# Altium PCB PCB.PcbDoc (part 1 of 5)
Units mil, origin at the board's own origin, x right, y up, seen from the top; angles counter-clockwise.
Board outline 8070.87 x 4448.94 mil, 4 copper layers (Top Layer, Layer 1, Layer 2, Bottom Layer), stack 23.756 mil thick; 263 components, 330 nets, 1677 pads, 1186 vias.
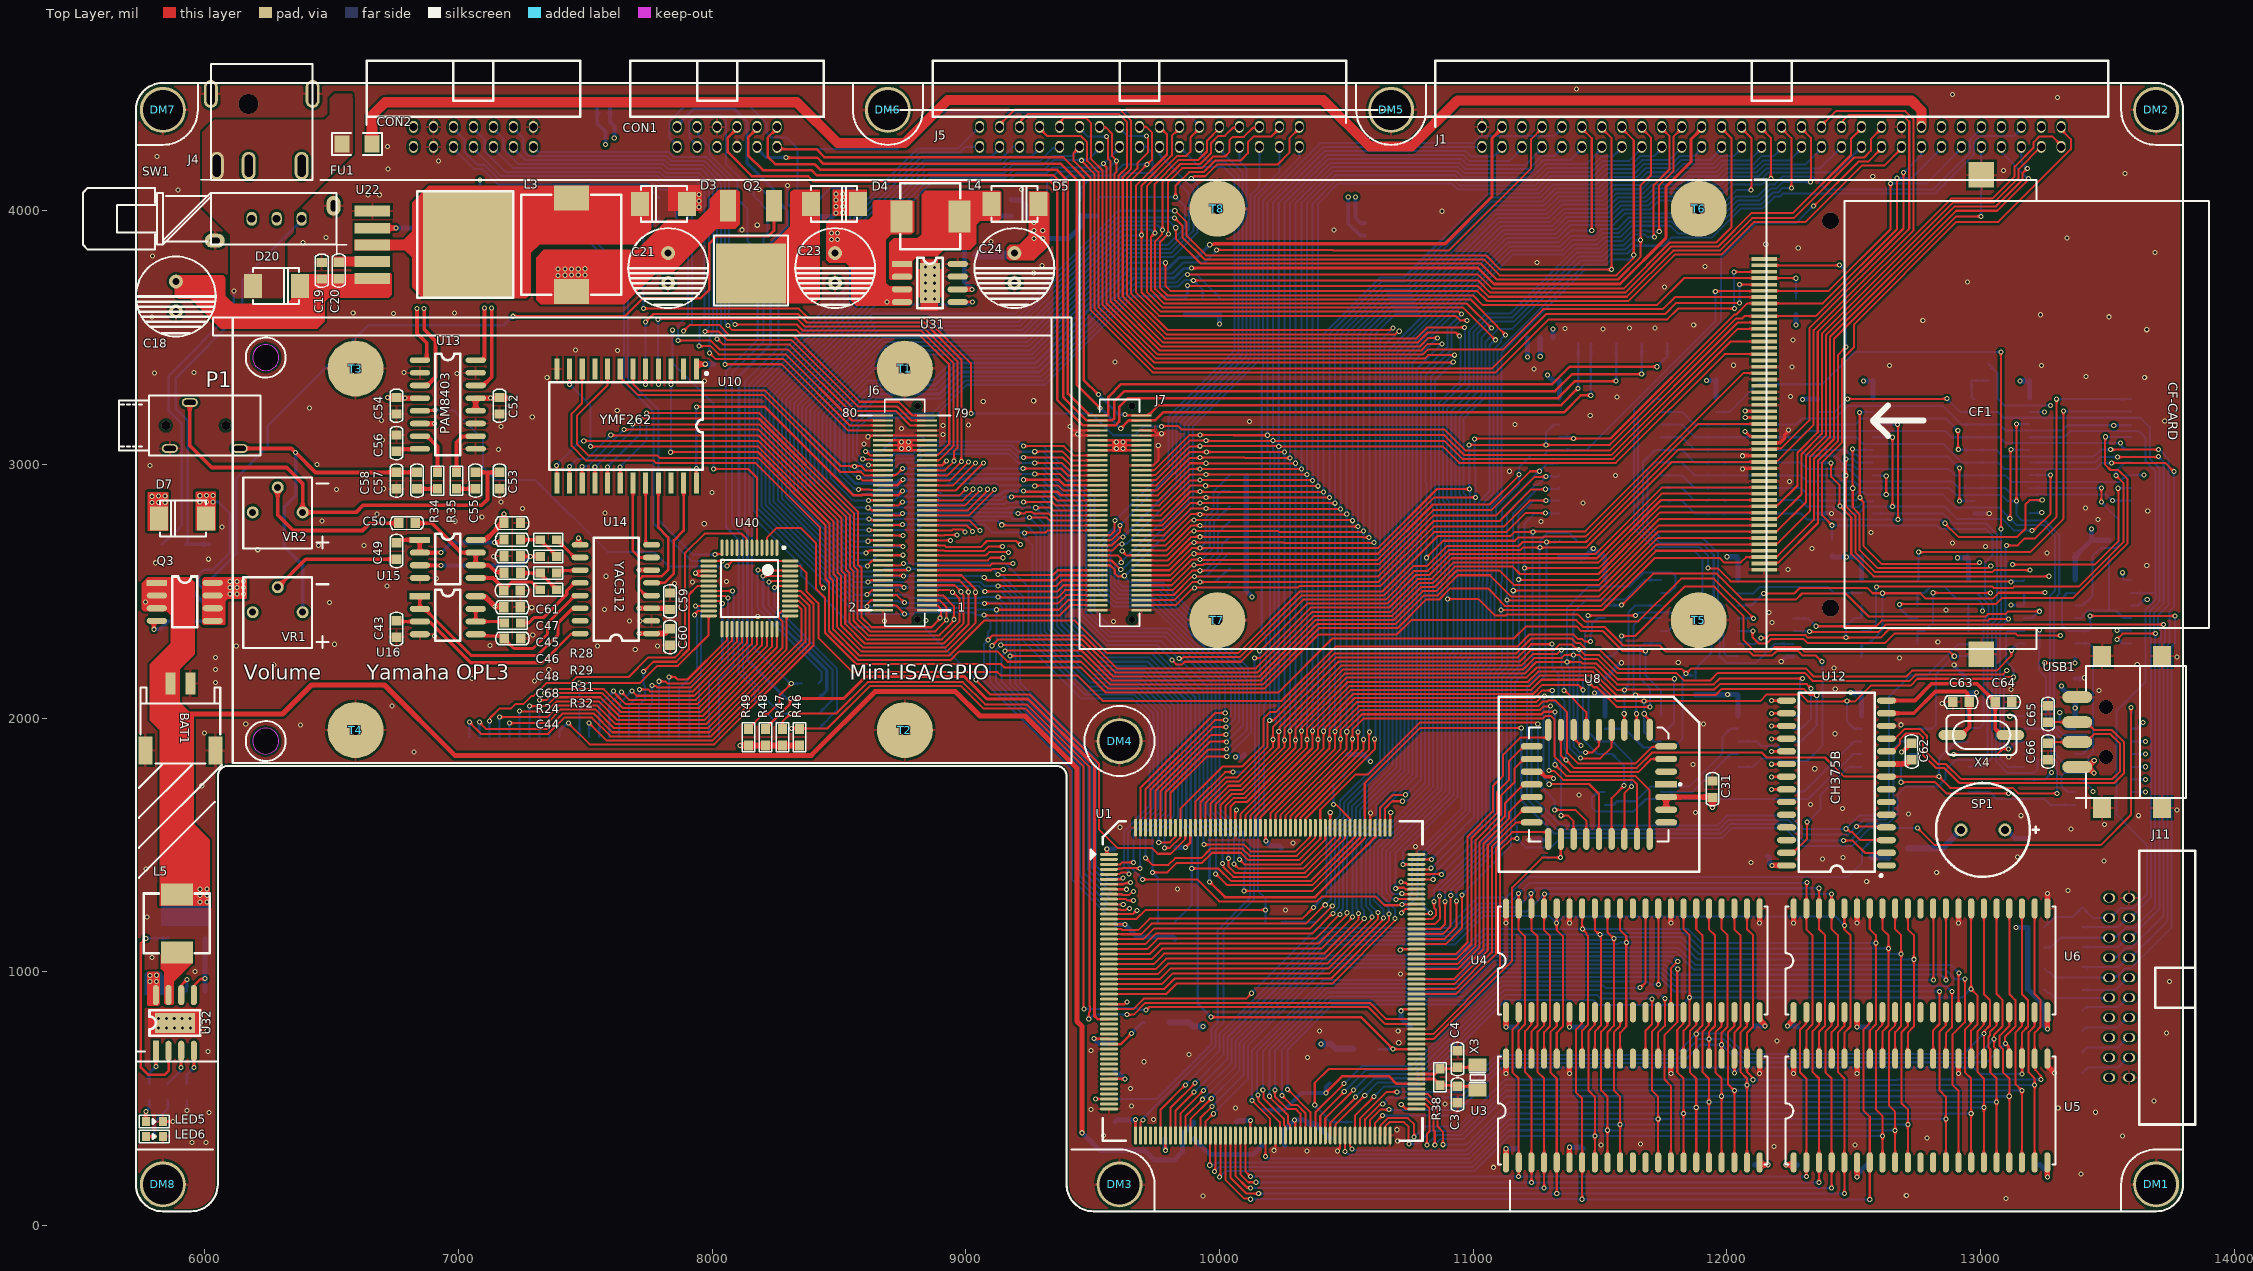
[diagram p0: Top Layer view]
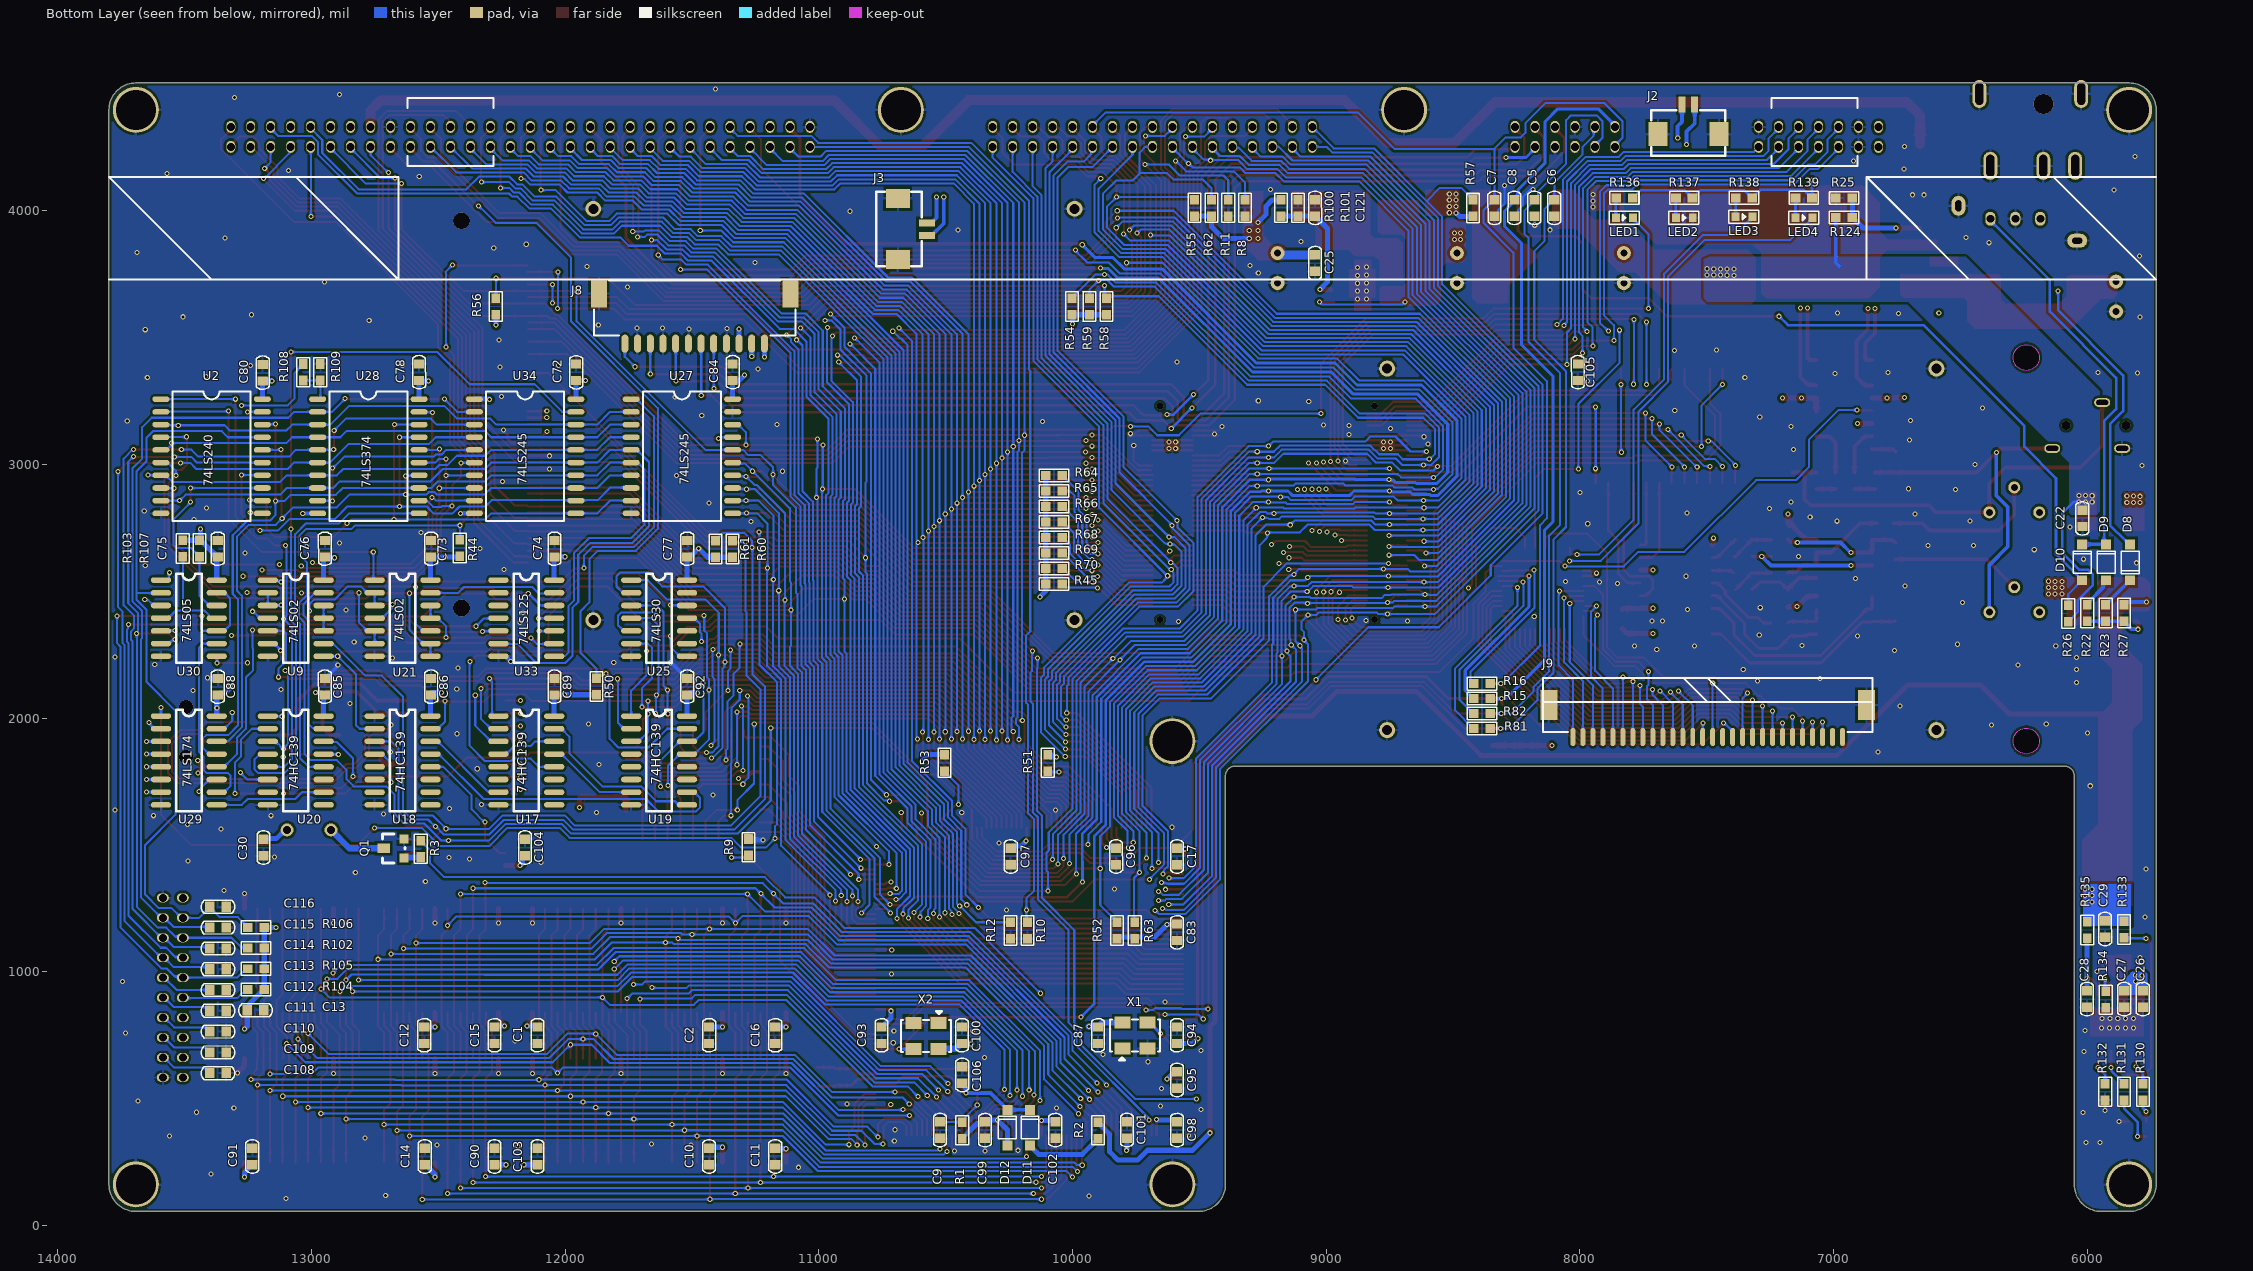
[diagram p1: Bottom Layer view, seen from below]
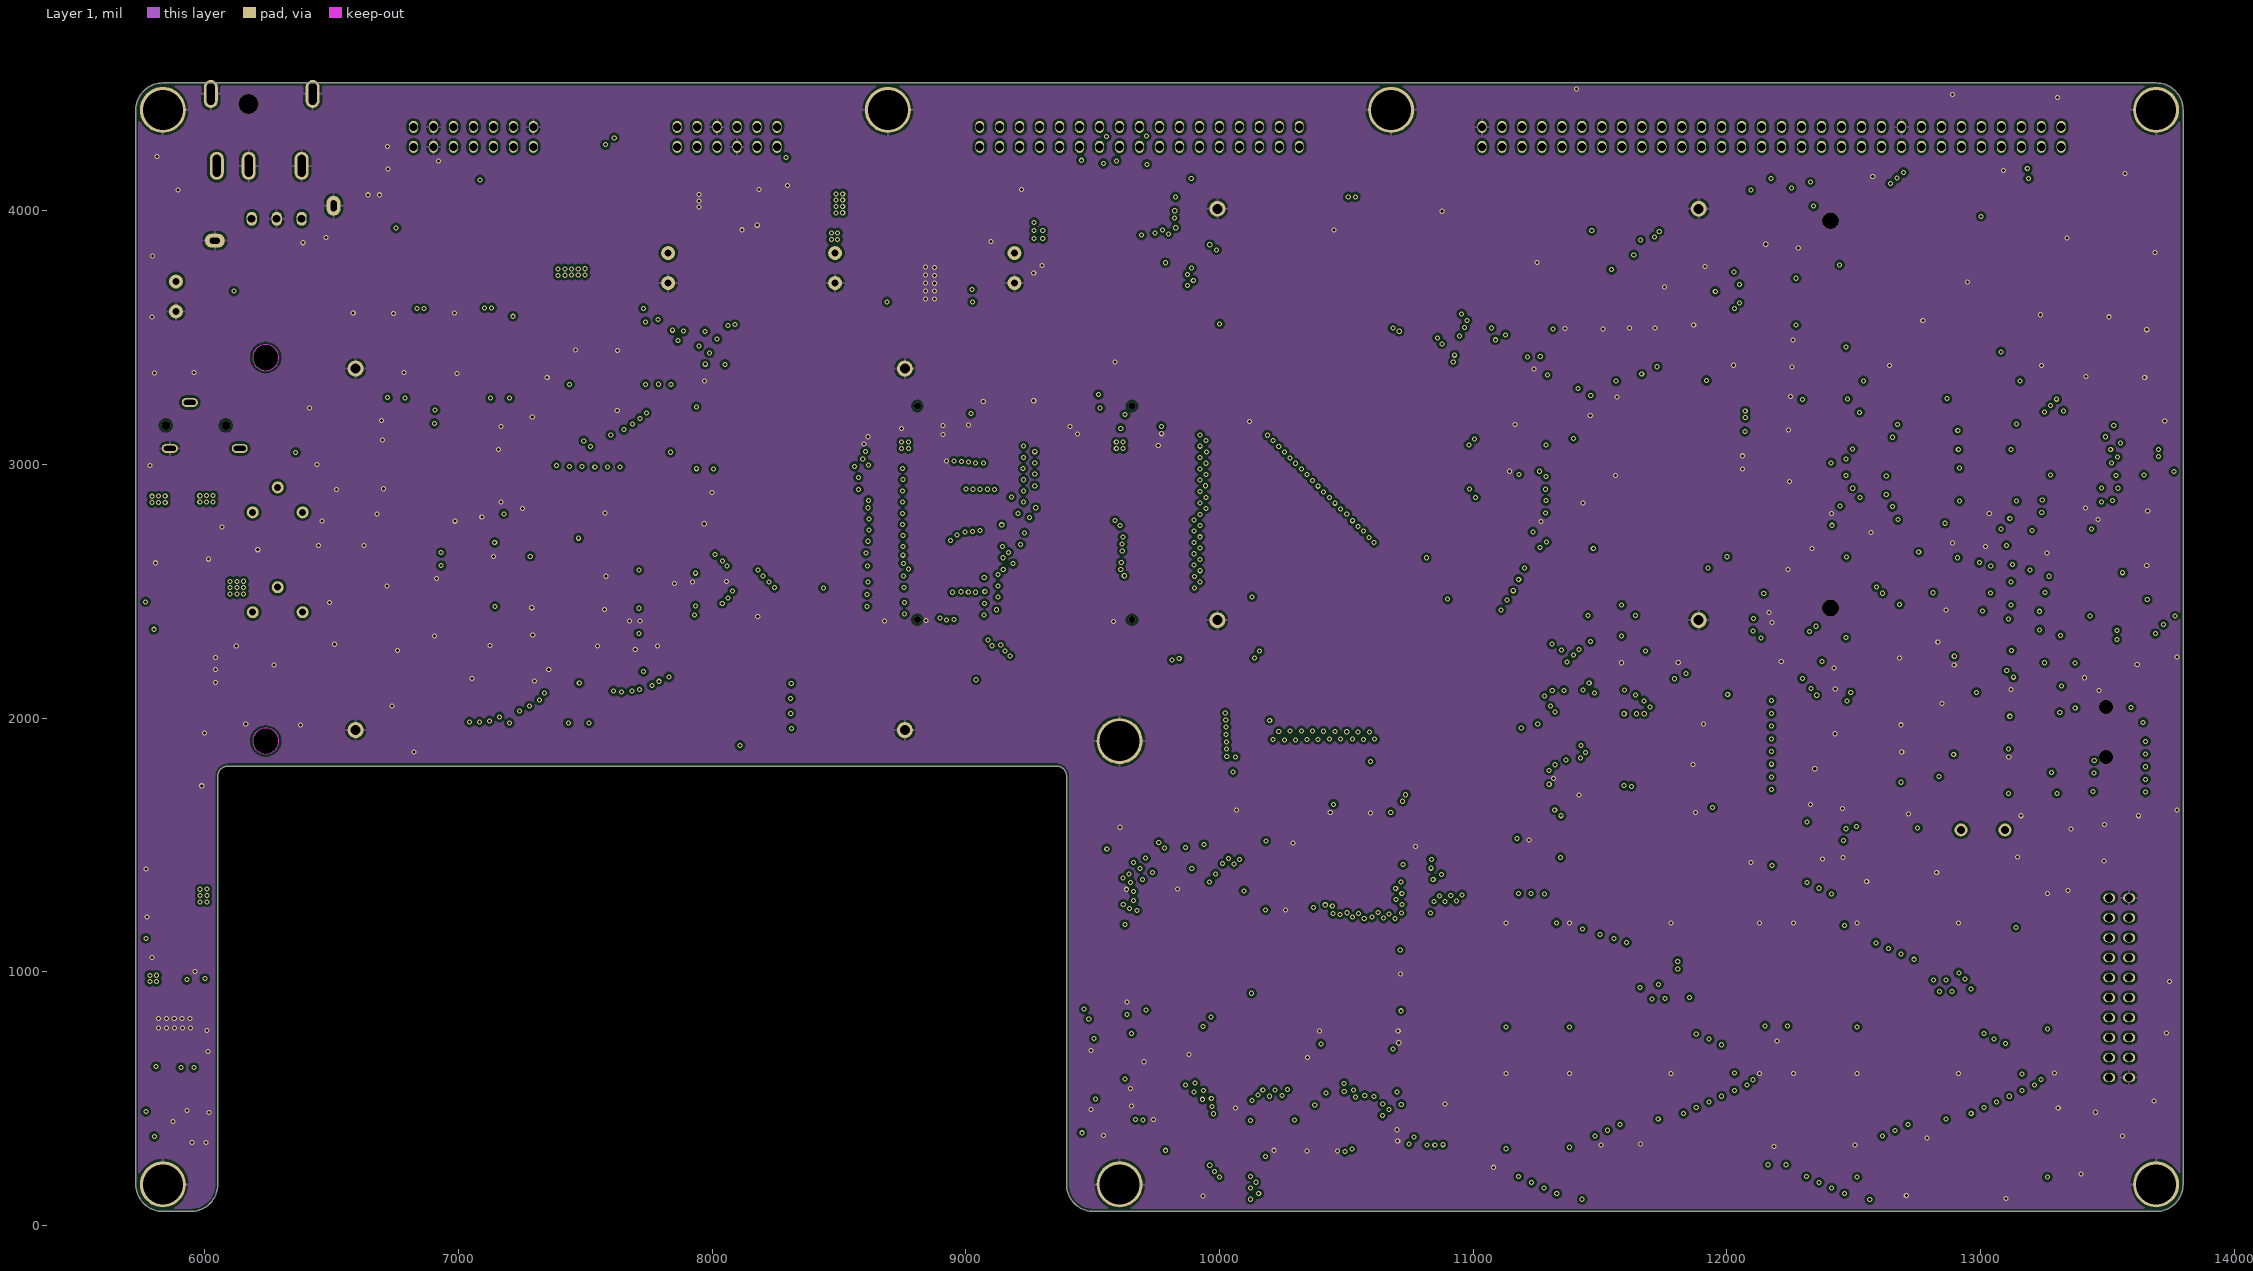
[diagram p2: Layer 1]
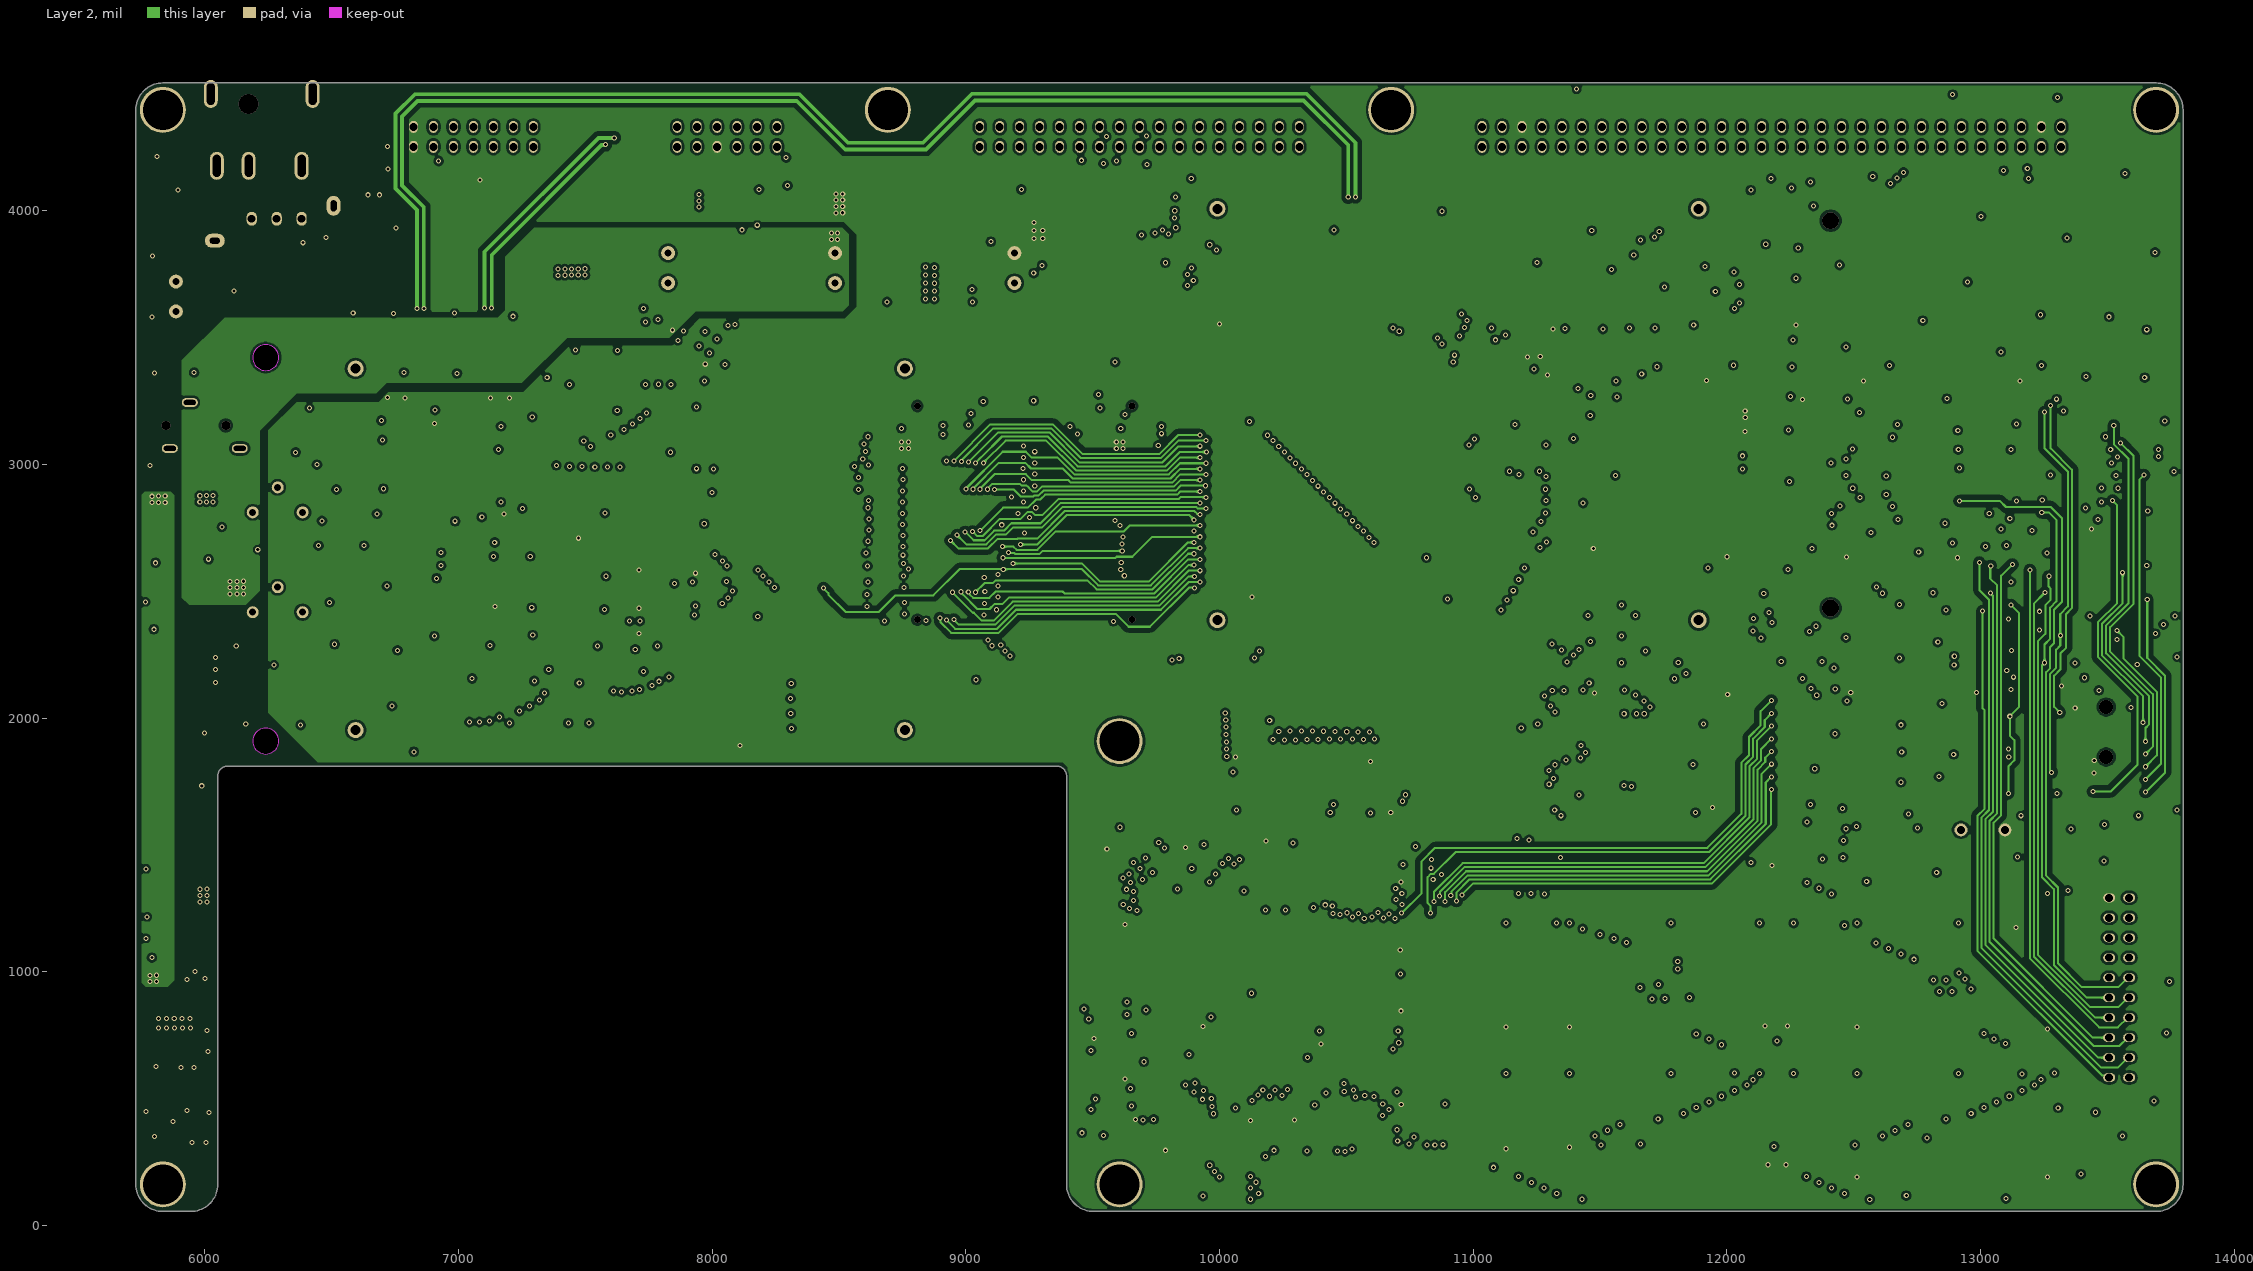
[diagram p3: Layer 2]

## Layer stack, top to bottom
Top Solder: solder mask 0.4, Solder Resist, Dk 3.5
Top Layer: signal copper 1.4
Dielectric 1: prepreg 2.8, PP-006, Dk 4.1
Layer 1: signal copper 1.378
Dielectric1: dielectric 12.6, FR-4, Dk 4.8
Layer 2: signal copper 1.378
Dielectric 2: prepreg 2.8, PP-006, Dk 4.1
Bottom Layer: signal copper 1.4
Bottom Solder: solder mask 0.4, Solder Resist, Dk 3.5

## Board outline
5834.65,54.99 5944.88,54.99 ccw(c5944.88,161.29) 6051.18,161.29 6051.18,1771.53 cw(c6090.55,1771.53) 6090.55,1810.9 9358.27,1810.9 cw(c9358.27,1771.53) 9397.64,1771.53 9397.64,1771.65 9397.64,161.42 ccw(c9503.94,161.42) 9503.94,55.12 13692.91,55.12 ccw(c13692.91,161.42) 13799.21,161.42 13799.21,4397.64 ccw(c13692.91,4397.64) 13692.91,4503.94 5834.65,4503.94 ccw(c5834.65,4397.64) 5728.35,4397.64 5728.35,161.29 ccw(c5834.65,161.29)
cut-out: 6188.98,1909.45 ccw(c6240.16,1909.45) 6240.16,1858.27 ccw(c6240.16,1909.45) 6291.34,1909.45 ccw(c6240.16,1909.45) 6240.16,1960.63 ccw(c6240.16,1909.45)
cut-out: 6188.98,3421.26 ccw(c6240.16,3421.26) 6240.16,3370.08 ccw(c6240.16,3421.26) 6291.34,3421.26 ccw(c6240.16,3421.26) 6240.16,3472.44 ccw(c6240.16,3421.26)

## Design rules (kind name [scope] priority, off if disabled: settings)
BoardOutlineClearance [All] p1: gap=0 ignorepadtopadclearanceinfootprint=FALSE except(10: Poly-OutlineEdge Poly-CavityEdge Poly-CutoutEdge Poly-SplitBarrior)
Clearance Clearance_1 [OnLayer('Layer 2') vs InNet('VCC')] p1: gap=8 ignorepadtopadclearanceinfootprint=TRUE except(20: Arc-Fill Arc-Poly Arc-Region Track-Fill Track-Poly Track-Region SMDPad-Fill SMDPad-Poly SMDPad-Region THPad-Fill THPad-Poly THPad-Region Via-Fill Via-Poly Via-Region Fill-Fill Fill-Poly Fill-Region Poly-Poly Poly-Region Region-Region)
Clearance [All] p2: gap=8 ignorepadtopadclearanceinfootprint=FALSE except(7: SMDPad-SMDPad; 10: Arc-Fill Arc-Poly Arc-Region Track-Fill Track-Poly Track-Region SMDPad-Fill SMDPad-Poly SMDPad-Region THPad-Fill THPad-Poly THPad-Region Via-Fill Via-Poly Via-Region Fill-Fill Fill-Poly Fill-Region Poly-Poly Poly-Region Region-Region)
ComponentClearance [All] p1: gap=0 collisioncheckmode=3 verticalgap=0 showdistances=FALSE
HoleSize [All] p1: absolutevalues=TRUE maxlimit=1000 minlimit=1 maxpercent=80.000 minpercent=20.000
HoleToHoleClearance [All] p1: gap=0 allowstackedmicrovias=TRUE
MinimumSolderMaskSliver [All] p1: minsoldermaskwidth=0
PlaneClearance [All] p1: clearance=0
PolygonConnect PolygonConnect_1 [InNet('GND')] p1: thpad.connectstyle=Relief thpad.reliefconductorwidth=10 thpad.reliefentries=4 thpad.polygonreliefangle="90 Angle" thpad.airgapwidth=10 smdpad.connectstyle=Relief smdpad.reliefconductorwidth=10 smdpad.reliefentries=4 smdpad.polygonreliefangle="90 Angle" smdpad.airgapwidth=10 via.connectstyle=Direct via.reliefconductorwidth=10 via.reliefentries=4 via.polygonreliefangle="90 Angle" via.airgapwidth=10
PolygonConnect [All] p2: connectstyle=Direct reliefconductorwidth=10 reliefentries=4 polygonreliefangle="90 Angle" airgapwidth=10
RoutingVias [All] p1: holewidth=12 width=20 viastyle="Through Hole" minholewidth=12 minwidth=20 maxholewidth=12 maxwidth=20
SilkToSilkClearance [All] p1: silktosilkclearance=0
SilkToSolderMaskClearance [IsPad] p1: minsilkscreentomaskgap=0 clearancetoexposedcopper=TRUE
SolderMaskExpansion [All] p1: expansion=4 istentingtop=FALSE
Width [All] p1: maxlimit=200 minlimit=8 preferedwidth=8 toplayer_maxwidth=50 bottomlayer_maxwidth=50 minimp=50.000000 maximp=50.000000 favimp=50.000000
23 further rules are at their usual default settings.

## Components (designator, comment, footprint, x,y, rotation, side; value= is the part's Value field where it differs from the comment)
BAT1 "PH2.0卧贴2P" PH-2B 5746,2058 r270 top locked
C1 "0.1uf" C0603 12109.75,717 r90 bottom
C2 "0.1uf" C0603 11433,717 r90 bottom
C3 "10pf" C0603 10939,548 r270 top
C4 "10pf" C0603 10939,687.98 r270 top
C5 "47pf" C0603 8179.5,4043.98 r270 bottom
C6 "47pf" C0603 8101,4043.98 r270 bottom
C7 "47pf" C0603 8337,4043.98 r270 bottom
C8 "47pf" C0603 8258.5,4043.98 r270 bottom
C9 "10uf" C0603 10523,343.02 r90 bottom
C10 "0.1uf" C0603 11433,303.96 r270 bottom
C11 "10uf" C0603 11172,303.96 r270 bottom
C12 "10uf" C0603 12556,781.96 r270 bottom
C13 "0.1uf" C0603 13254,848 r180 bottom
C14 "10uf" C0603 12554,239 r90 bottom
C15 "0.1uf" C0603 12279,781.96 r270 bottom
C16 "0.1uf" C0603 11172.25,781.96 r270 bottom
C17 "0.1uf" C0603 9588,1487 r270 bottom
C18 "470uf" CD8 5886,3662 r90 top locked
C19 "1uf" C0603 6461,3731 r90 top
C20 "1uf" C0603 6528,3732 r90 top
C21 "470uf" CD8 7826.77,3774 r90 top
C22 "1uf" C0603 6019,2820 r270 bottom
C23 "470uf" CD8 8485,3774 r90 top
C24 "470uf" CD8 9192,3774 r90 top
C25 "1uf" C0603 9044,3826 r270 bottom
C26 "1uf" C0603 5780.53,924.56 r270 bottom
C27 "22uf" C0603 5854.02,924.56 r270 bottom
C28 "22uf" C0603 6001,924.56 r270 bottom
C29 "22uf" C0603 5929.13,1200.79 r270 bottom
C30 "0.1uf" C0603 13190,1522 r270 bottom
C31 "0.1uf" C0603 11944,1687 r90 top
C43 "10uf" C0603 6755.91,2319.02 r90 top
C44 "47pf" C0603 7180.02,2314 r0 top
C45 "2.7nf" C0603 7179.51,2638.13 r0 top
C46 "2.7nf" C0603 7179.51,2572.88 r0 top
C47 "2.7nf" C0603 7179.51,2703.38 r0 top
C48 "2.7nf" C0603 7244,2503 r180 top
C49 "1uf" C0603 6756.16,2691 r270 top
C50 "1uf" C0603 6829.24,2768.38 r180 top
C52 "1uf" C0603 7161.42,3198.8 r90 top
C53 "0.1uf" C0603 7161.42,2903.54 r90 top
C54 "1uf" C0603 6755.91,3198.8 r90 top
C55 "1uf" C0603 7066.93,2968.5 r270 top
C56 "0.1uf" C0603 6755.91,3051.17 r90 top
C57 "1uf" C0603 6837,2968.5 r270 top
C58 "0.1uf" C0603 6755.91,2903.54 r90 top
C59 "10uf" C0603 7834.25,2492.98 r270 top
C60 "0.1uf" C0603 7834,2287.02 r90 top
C61 "1uf" C0603 7244.47,2768.38 r180 top
C62 "0.1uf" C0603 12729,1836.04 r90 top
C63 "30pf" C0603 12891.71,2062.99 r0 top
C64 "30pf" C0603 13124.04,2062.99 r180 top
C65 "30pf" C0603 13266.75,1983.53 r90 top
C66 "30pf" C0603 13267,1901 r270 top
C68 "1uf" C0603 7179.02,2437 r0 top
C72 "0.1uf" C0603 11957.32,3330.7 r90 bottom
C73 "0.1uf" C0603 12529,2635 r90 bottom
C74 "0.1uf" C0603 12043,2635 r90 bottom
C75 "0.1uf" C0603 13370,2635 r90 bottom
C76 "0.1uf" C0603 12948,2635 r90 bottom
C77 "0.1uf" C0603 11519,2635 r90 bottom
C78 "0.1uf" C0603 12576.38,3331 r90 bottom
C80 "10uf" C0603 13193,3329.02 r90 bottom
C83 "10uf" C0603 9588,1188 r270 bottom
C84 "0.1uf" C0603 11340.16,3331 r90 bottom
C85 "10uf" C0603 12948,2091 r90 bottom
C86 "10uf" C0603 12529,2091 r90 bottom
C87 "0.1uf" C0603 9900,781.96 r270 bottom
C88 "0.1uf" C0603 13370,2091 r90 bottom
C89 "0.1uf" C0603 12043,2091 r90 bottom
C90 "0.1uf" C0603 12279,239 r90 bottom
C91 "0.1uf" C0603 13234,239 r90 bottom
C92 "0.1uf" C0603 11519,2091 r90 bottom
C93 "0.1uf" C0603 10753,781.96 r270 bottom
C94 "0.1uf" C0603 9588.25,717 r90 bottom
C95 "0.1uf" C0603 9588,606 r270 bottom
C96 "0.1uf" C0603 9828.26,1487 r270 bottom
C97 "0.1uf" C0603 10244,1486.98 r270 bottom
C98 "0.1uf" C0603 9588,408 r270 bottom
C99 "0.1uf" C0603 10345,407.98 r270 bottom
C100 "0.1uf" C0603 10436,717 r90 bottom
C101 "0.1uf" C0603 9786,343.04 r90 bottom
C102 "0.1uf" C0603 10068,408 r270 bottom
C103 "0.1uf" C0603 12110,239 r90 bottom
C104 "0.1uf" C0603 12159,1522 r270 bottom
C105 "1uf" C0603 8008,3331 r90 bottom
C106 "22uf" C0603 10435,560 r90 bottom
C108 "0.0022uf" C0603 13402,600 r180 bottom
C109 "0.0022uf" C0603 13402,681.99 r180 bottom
C110 "0.0022uf" C0603 13402,763.98 r180 bottom
C111 "0.0022uf" C0603 13402,845.96 r180 bottom
C112 "0.0022uf" C0603 13402,927.95 r180 bottom
C113 "0.0022uf" C0603 13402,1009.94 r180 bottom
C114 "0.0022uf" C0603 13402,1091.93 r180 bottom
C115 "0.0022uf" C0603 13402,1173.92 r180 bottom
C116 "0.0022uf" C0603 13402,1255.9 r180 bottom
C121 "30pf" C0603 9044,3979 r90 bottom
CF1 "CF-CARD" CF-CARD-B 12157.48,4122.05 r0 top locked
CON1 "CON6x2" IDC2x6(2.0)B 7677.17,4370.08 r0 top locked
CON2 "CON7x2" IDC2x7(2.0)B 6637.8,4370.08 r0 top locked
D3 "SS54" DO-214B(SMB) 7901.57,4027.56 r180 top
D4 "SS54" DO-214B(SMB) 8389.76,4027.56 r0 top
D5 "SS54" DO-214B(SMB) 9102.36,4027.56 r0 top
D7 "SS54" DO-214B(SMB) 6003.94,2787.4 r180 top
D8 "1N5819" SOD123 5830.71,2685.04 r270 bottom
D9 "1N5819" SOD123 5925.2,2543.31 r90 bottom
D10 "1N5819" SOD123 6019.68,2543.31 r90 bottom
D11 "1N5819" SOD123 10168,314 r90 bottom
D12 "1N5819" SOD123 10257,314 r90 bottom
D20 "SS54" DO-214B(SMB) 6190,3703 r0 top
DM1 "CON1" M-4 13692.91,161.42 r0 top locked
DM2 "CON1" M-4 13692.91,4397.64 r0 top locked
DM3 "CON1" M-4 9606.3,161.42 r0 top locked
DM4 "CON1" M-4 9606.3,1909.45 r0 top locked
DM5 "CON1" M-4 10677.17,4397.64 r0 top locked
DM6 "CON1" M-4 8692.91,4397.64 r0 top locked
DM7 "CON1" M-4 5834.65,4397.64 r0 top locked
DM8 "CON1" M-4 5834.64,161.42 r0 top
FU1 "0" 1206 6541,4263 r0 top
J1 "CON30x2B" IDC2X30(2.0)B 10850.39,4370.08 r0 top locked
J2 "1.25mm卧贴2P" 1.25mmB-2P 7597.44,4418.31 r180 bottom locked
J3 "1.25mm卧贴2P" 1.25mmB-2P 10573.98,3952.09 r270 bottom locked
J4 "DCIN" DC5.5-044 6425.2,4122.05 r90 top locked
J5 "CON17X2" IDC2x17(2.0)B 8870.08,4370.08 r0 top locked
J6 "CON40x2" BTB0.5-80P 8838.58,2425.2 r90 top locked
J7 "CON40x2" BTB0.5-80P 9685.04,2425.2 r90 top locked
J8 "CON12" 1.25mm-MX12P 11214.96,3476.38 r0 bottom locked
J9 "CON28" FCP1.0-28A 7496.06,2157.48 r180 bottom locked
J11 "CON10x2" IDC2x10(2.0)B 13625.98,1476.38 r270 top locked
L3 "47uH" L1010 7444.88,3681.1 r90 top
L4 "2R2" L7x7 8971,3978 r180 top
L5 "2R2" L7x7 5890,1300.41 r270 top
LED1 "BLUE" LED0603 7858.27,3972.44 r180 bottom locked
LED2 "RED" LED0603 7622.05,3972.44 r180 bottom locked
LED3 "BLUE" LED0603 7385.83,3976.38 r180 bottom locked
LED4 "RED" LED0603 7149.61,3972.44 r180 bottom locked
LED5 "CHRG" LED0603 5767.72,409.45 r0 top
LED6 "STDBY" LED0603 5767.72,350.39 r0 top
P1 "AUDIO-3.5MM" AUDIO1 6212.6,3263.78 r0 top locked
Q1 "2N3904(1AM)" SOT23 12676.29,1486.17 r90 bottom
Q2 "AOD403" TO-252-MOS 8244.09,4019.69 r180 top
Q3 "AO4453" SO-8 5811.02,2533.07 r0 top
R1 "30k" R0603 10435,342 r90 bottom
R2 "220" R0603 9900,407 r270 bottom
R3 "1k" R0603 12570,1517 r270 bottom
R8 "4.7k" R0603 9320,3979 r90 bottom
R9 "4.7k" R0603 11278,1523 r270 bottom
R10 "4.7k" R0603 10178,1130 r90 bottom
R11 "4.7k" R0603 9386.33,3979 r90 bottom
R12 "4.7k" R0603 10245,1130 r90 bottom
R15 "220" R0603 8353.61,2076.5 r0 bottom
R16 "220" R0603 8353.61,2135.55 r0 bottom
R22 "590" R0603 6000,2446.89 r270 bottom
R23 "1k" R0603 5927.17,2446.89 r270 bottom
R24 "33" R0603 7246,2375 r180 top
R25 "1k" R0603 6926,4050 r0 bottom
R26 "30k" R0603 6074.8,2444.88 r270 bottom
R27 "30k" R0603 5854.33,2381.89 r90 bottom
R28 "4.7k" R0603 7387,2703 r180 top
R29 "4.7k" R0603 7387,2637.33 r180 top
R31 "4.7k" R0603 7387,2571.67 r180 top
R32 "4.7k" R0603 7387,2506 r180 top
R34 "4.7k" R0603 6917.32,2903.5 r90 top
R35 "4.7k" R0603 6992.13,2968.5 r270 top
R38 "1M(NC)" R0603 10870,617 r270 top
R44 "4.7k" R0603 12416,2703 r270 bottom
R45 "4.7k" R0603 10041,2529 r0 bottom
R46 "4.7k" R0603 8344,1957 r270 top
R47 "4.7k" R0603 8277.33,1957 r270 top
R48 "4.7k" R0603 8210.67,1957 r270 top
R49 "4.7k" R0603 8144,1957 r270 top
R50 "4.7k" R0603 11877,2157 r270 bottom
R51 "4.7k" R0603 10098,1791 r90 bottom
R52 "4.7k" R0603 9825,1195 r270 bottom
R53 "4.7k" R0603 10505,1791 r90 bottom
R54 "4.7k" R0603 10002,3655 r270 bottom
R55 "4.7k" R0603 9519,4044 r270 bottom
R56 "4.7k" R0603 12274,3655 r270 bottom
R57 "4.7k" R0603 8422,4043 r270 bottom
R58 "4.7k" R0603 9866,3655 r270 bottom
R59 "4.7k" R0603 9934,3655 r270 bottom
R60 "4.7k" R0603 11341,2699 r270 bottom
R61 "4.7k" R0603 11408,2699 r270 bottom
R62 "4.7k" R0603 9452.67,4044 r270 bottom
R63 "4.7k" R0603 9755,1195 r270 bottom
R64 "4.7k" R0603 10041,2956 r0 bottom
R65 "4.7k" R0603 10041,2895 r0 bottom
R66 "4.7k" R0603 10041,2834 r0 bottom
R67 "4.7k" R0603 10041,2773 r0 bottom
R68 "4.7k" R0603 10041,2712 r0 bottom
R69 "4.7k" R0603 10041,2651 r0 bottom
R70 "4.7k" R0603 10041,2590 r0 bottom
R81 "220" R0603 8353.61,1958.39 r0 bottom
R82 "220" R0603 8353.61,2017.44 r0 bottom
R100 "30k" R0603 9177.86,4044 r270 bottom
R101 "10k" R0603 9110.93,3979 r90 bottom
R102 "4.7k" R0603 13251.97,1093.27 r180 bottom
R103 "4.7k" R0603 13508,2636 r90 bottom
R104 "4.7k" R0603 13251.97,929.82 r180 bottom
R105 "4.7k" R0603 13251.97,1011.55 r180 bottom
R106 "4.7k" R0603 13252,1175 r180 bottom
R107 "4.7k" R0603 13442,2636 r90 bottom
R108 "0R" R0603 13033,3396 r270 bottom
R109 "4.7k" R0603 12966,3396 r270 bottom
R124 "3.3k" R0603 6926.09,3973 r0 bottom
R130 "1k" R0603 5780.2,493.8 r90 bottom
R131 "1k" R0603 5854.67,493.8 r90 bottom
R132 "51k" R0603 5929.13,493.8 r90 bottom
R133 "1k" R0603 5855,1198.86 r270 bottom
R134 "91k" R0603 5927,922.43 r270 bottom
R135 "0.5R" R0603 6000,1131.85 r90 bottom
R136 "4.7k" R0603 7792,4051 r0 bottom
R137 "4.7k" R0603 7556.33,4051 r0 bottom
R138 "4.7k" R0603 7320.67,4051 r0 bottom
R139 "4.7k" R0603 7085,4051 r0 bottom
SP1 "无源蜂鸣器(9055-42Ω)" "BELL - 9MM" 13097,1559 r180 top locked
SW1 "POWER" SW3 6519.69,4070.87 r180 top locked
T1 "D5xH4" M2.5-D5xH4 8759.84,3377.95 r0 top locked
T2 "D5xH4" M2.5-D5xH4 8759.84,1952.76 r0 top locked
T3 "D5xH4" M2.5-D5xH4 6594.49,3377.95 r0 top locked
T4 "D5xH4" M2.5-D5xH4 6594.49,1952.76 r0 top locked
T5 "D5xH4" M2.5-D5xH4 11889.76,2385.83 r0 top locked
T6 "D5xH4" M2.5-D5xH4 11889.76,4007.87 r0 top locked
T7 "D5xH4" M2.5-D5xH4 9992.13,2385.83 r0 top locked
T8 "D5xH4" M2.5-D5xH4 9992.13,4007.87 r0 top locked
U1 "M6117C" QFP208 9564.65,1462.91 r270 top locked
U2 "74LS240" SOP20B 13594.49,3257.09 r180 bottom locked
U3 "4C161024C" SOJ-42 11130,248 r90 top locked
U4 "4C161024C" SOJ-42 11130,840 r90 top locked
U5 "4C161024C" SOJ-42 12264,248 r90 top locked
U6 "4C161024C" SOJ-42 12264,840 r90 top locked
U8 "29C512_PLCC32" PLCC32S1 11761.46,1738.62 r270 top locked
U9 "74LS02" SO-14 13172.76,2543.7 r180 bottom
U10 "YMF262" SOP24-B 7938,3383.69 r180 top locked
U12 "CH375B" SOP-28 12629.92,1418.9 r90 top locked
U13 "PAM8403" SO-16 6848,3411.2 r0 top
U14 "YAC512" SOP16 7761.34,2333 r180 top
U15 "MC33502DR" SO-8 6848,2702.38 r0 top
U16 "MC33502DR" SO-8 6848,2480.38 r0 top
U17 "74HC139" SO-16 12263.78,2007.8 r180 bottom locked
U18 "74HC139" SO-16 12751.5,2007.8 r180 bottom
U19 "74HC139" SO-16 11740.16,2007.8 r180 bottom locked
U20 "74HC139" SO-16 13172.76,2007.8 r180 bottom
U21 "74LS02" SO-14 12751.5,2543.7 r180 bottom
U22 "XL4015" TO-263(T) 6660.43,3999.14 r270 top
U25 "74LS30" SO-14 11740.16,2543.7 r180 bottom locked
U27 "74LS245" SOP20B 11740.16,3257.09 r180 bottom locked
U28 "74LS374" SOP20B 12976.38,3257.09 r180 bottom locked
U29 "74LS174" SO-16 13594.02,2007.8 r180 bottom
U30 "74LS05" SO-14 13594.02,2543.7 r180 bottom locked
U31 "XR2981" "SO-8 A" 8748.5,3790.16 r0 top locked
U32 "IP2312" "SO-8 A" 5807,688 r90 top
U33 "74LS125" SO-14 12263.78,2543.7 r180 bottom
U34 "74LS245" SOP20B 12358.27,3257.09 r180 bottom locked
U40 "BK82C42" LQFP48 8147,2511 r270 top
USB1 "USB_A" USBA-S 13417.32,1685.04 r0 top locked
VR1 "10k" VR3362 6151.57,2275.59 r0 top
VR2 "10k" VR3362 6151.57,2669.29 r0 top
X1 "80M(有源5V)" CRY-5032 9852.43,685.83 r180 bottom
X2 "14.318M(有源5V)" CRY-5032 10479.57,809.81 r0 bottom
X3 "32768Hz" CRY3215A 11018,533 r90 top
X4 "12M" CRY-49S-mini 12866.14,1854.33 r0 top

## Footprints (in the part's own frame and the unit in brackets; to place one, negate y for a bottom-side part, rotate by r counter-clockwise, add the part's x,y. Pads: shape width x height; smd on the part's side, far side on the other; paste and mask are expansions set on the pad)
1.25mm-MX12P [mm] "卧贴"
  rect 1.6x2.8 smd: 0(-2.615,-5) 0(16.585,-5)
  oval 0.7x1.8 smd: 1(0,0) 2(1.27,0) 3(2.54,0) 4(3.81,0) 5(5.08,0) 6(6.35,0) 7(7.62,0) 8(8.89,0) 9(10.16,0) 10(11.43,0) 11(12.7,0) 12(13.97,0)
  silkscreen extent -3.12,-6.3 17.09,-0.8
1.25mmB-2P [mm] "卧贴"
  rect 1.9x2.4 smd: 0(-2.425,-2.925) 0(3.683,-2.921)
  rect 0.7x1.6 smd: 1(0,0) 2(1.27,0)
  silkscreen extent -3.1,-5.1 4.35,-0.55
1206 [mm]
  rect 1.524x1.7 smd: 1(0,0) 2(3,0)
  silkscreen extent -1,-1.1 4,1.1
AUDIO1 [mm]
  oval 1.6x0.9 hole 0.5 slot 1.2 at 0 deg: 1(-8.9,-5.1) 2(-6.9,-0.5) 3(-1.9,-5.1)
  silkscreen extent -14,-5.8 0.2,0.2
"BELL - 9MM" [mm]
  round 1.3 hole 0.8: 1(0,0) 2(4.4,0)
  silkscreen extent -3.4,-4.7 6.9,4.7
BTB0.5-80P [mm]
  rect 0.24x2 smd: 1(0,-0.2) 2(0,4.2) 3(0.5,-0.2) 4(0.5,4.2) 5(1,-0.2) 6(1,4.2) 7(1.5,-0.2) 8(1.5,4.2) 9(2,-0.2) 10(2,4.2) 11(2.5,-0.2) 12(2.5,4.2) 13(3,-0.2) 14(3,4.2) 15(3.5,-0.2) 16(3.5,4.2) 17(4,-0.2) 18(4,4.2) 19(4.5,-0.2) 20(4.5,4.2) 21(5,-0.2) 22(5,4.2) 23(5.5,-0.2) 24(5.5,4.2) 25(6,-0.2) 26(6,4.2) 27(6.5,-0.2) 28(6.5,4.2) 29(7,-0.2) 30(7,4.2) 31(7.5,-0.2) 32(7.5,4.2) 33(8,-0.2) 34(8,4.2) 35(8.5,-0.2) 36(8.5,4.2) 37(9,-0.2) 38(9,4.2) 39(9.5,-0.2) 40(9.5,4.2) 41(10,-0.2) 42(10,4.2) 43(10.5,-0.2) 44(10.5,4.2) 45(11,-0.2) 46(11,4.2) 47(11.5,-0.2) 48(11.5,4.2) 49(12,-0.2) 50(12,4.2) 51(12.5,-0.2) 52(12.5,4.2) 53(13,-0.2) 54(13,4.2) 55(13.5,-0.2) 56(13.5,4.2) 57(14,-0.2) 58(14,4.2) 59(14.5,-0.2) 60(14.5,4.2) 61(15,-0.2) 62(15,4.2) 63(15.5,-0.2) 64(15.5,4.2) 65(16,-0.2) 66(16,4.2) 67(16.5,-0.2) 68(16.5,4.2) 69(17,-0.2) 70(17,4.2) 71(17.5,-0.2) 72(17.5,4.2) 73(18,-0.2) 74(18,4.2) 75(18.5,-0.2) 76(18.5,4.2) 77(19,-0.2) 78(19,4.2) 79(19.5,-0.2) 80(19.5,4.2)
  silkscreen extent -1.6,0 21.1,4
C0603 [mil]
  rect 37.01x40 smd: 1(0,0)
  rect 37x40 smd: 2(64.98,0)
  silkscreen extent -34,-25 98,25
CD8 [mm]
  round 1.4 hole 0.7: 1(1.5,0) 2(-1.5,0)
  silkscreen extent -4,-4 4,4
CF-CARD-B [mm]
  rect 2.54x2.54 smd: 0(21.5,-47.5) 0(21.5,0.5)
  rect 2.54x0.368 smd: 1(-0.25,-39.05) 2(-0.25,-37.78) 3(-0.25,-36.51) 4(-0.25,-35.24) 5(-0.25,-33.97) 6(-0.25,-32.7) 7(-0.25,-31.43) 8(-0.25,-30.16) 9(-0.25,-28.89) 10(-0.25,-27.62) 11(-0.25,-26.35) 12(-0.25,-25.08) 13(-0.25,-23.81) 14(-0.25,-22.54) 15(-0.25,-21.27) 16(-0.25,-20) 17(-0.25,-18.73) 18(-0.25,-17.46) 19(-0.25,-16.19) 20(-0.25,-14.92) 21(-0.25,-13.65) 22(-0.25,-12.38) 24(-0.225,-9.84) 25(-0.225,-8.57) 26(-0.25,-38.415) 27(-0.25,-37.145) 28(-0.25,-35.875) 29(-0.25,-34.605) 30(-0.25,-33.335) 31(-0.25,-32.065) 32(-0.25,-30.795) 33(-0.25,-29.525) 34(-0.25,-28.255) 35(-0.25,-26.985) 36(-0.25,-25.715) 37(-0.25,-24.445) 38(-0.25,-23.175) 39(-0.25,-21.905) 40(-0.25,-20.635) 41(-0.25,-19.365) 42(-0.25,-18.095) 43(-0.25,-16.825) 44(-0.25,-15.555) 45(-0.25,-14.285) 46(-0.25,-13.015) 47(-0.25,-11.745) 49(-0.225,-9.205) 50(-0.225,-7.935)
  rect 2.54x0.356 smd: 23(-0.25,-11.11) 48(-0.225,-10.5)
  silkscreen extent 0,-47 44.3,0
CRY3215A [mm]
  rect 1.3x1.8 smd: 1(0,0) 2(2.54,0)
  silkscreen extent 0.76,-0.76 1.78,0.76
CRY-49S-mini [mm]
  oval 2.8x1 smd: 1(0.6,2) 2(6.4,2)
  silkscreen extent 0,0 7,4
CRY-5032 [mm]
  rect 1.6x1.2 smd: 1(1.23,0.3) 2(3.77,0.3) 3(3.77,2.9) 4(1.23,2.9)
  silkscreen extent 0,-0.9 5,3.2
DC5.5-044 [mm]
  oval 2.8x1.4 hole 0.8 slot 2.2 at 0 deg: 1(1.4,9.6) 2(1.4,6.4) 3(1.4,1.1) 3(8.6,0) 3(8.6,10.2)
  silkscreen extent 0,0 11.6,10.2
DO-214B(SMB) [mm]
  rect 1.8x2.4 smd: A(0,0) K(4.7,0)
  silkscreen extent 0,-1.8 4.6,1.8
FCP1.0-28A [mm]
  rect 1.7x3 smd: 0(-15.9,-2.7) 0(15.9,-2.7)
  oval 0.5x1.8 smd: 1(-13.5,-5.9) 2(-12.5,-5.9) 3(-11.5,-5.9) 4(-10.5,-5.9) 5(-9.5,-5.9) 6(-8.5,-5.9) 7(-7.5,-5.9) 8(-6.5,-5.9) 9(-5.5,-5.9) 10(-4.5,-5.9) 11(-3.5,-5.9) 12(-2.5,-5.9) 13(-1.5,-5.9) 14(-0.5,-5.9) 15(0.5,-5.9) 16(1.5,-5.9) 17(2.5,-5.9) 18(3.5,-5.9) 19(4.5,-5.9) 20(5.5,-5.9) 21(6.5,-5.9) 22(7.5,-5.9) 23(8.5,-5.9) 24(9.5,-5.9) 25(10.5,-5.9) 26(11.5,-5.9) 27(12.5,-5.9) 28(13.5,-5.9)
  silkscreen extent -16.5,-5.4 16.5,0
IDC2x6(2.0)B [mm]
  oval 0.9x1.2 hole 0.8: 1(4.7,-3) 2(4.7,-1) 3(6.7,-3) 4(6.7,-1) 5(8.7,-3) 6(8.7,-1) 7(10.7,-3) 8(10.7,-1) 9(12.7,-3) 10(12.7,-1) 11(14.7,-3) 12(14.7,-1)
  silkscreen extent 0,0 19.4,5.6
IDC2x7(2.0)B [mm]
  oval 0.9x1.2 hole 0.8: 1(4.7,-3) 2(4.7,-1) 3(6.7,-3) 4(6.7,-1) 5(8.7,-3) 6(8.7,-1) 7(10.7,-3) 8(10.7,-1) 9(12.7,-3) 10(12.7,-1) 11(14.7,-3) 12(14.7,-1) 13(16.7,-3) 14(16.7,-1)
  silkscreen extent 0,0 21.4,5.6
IDC2x10(2.0)B [mm]
  oval 0.9x1.2 hole 0.8: 1(4.7,-3) 2(4.7,-1) 3(6.7,-3) 4(6.7,-1) 5(8.7,-3) 6(8.7,-1) 7(10.7,-3) 8(10.7,-1) 9(12.7,-3) 10(12.7,-1) 11(14.7,-3) 12(14.7,-1) 13(16.7,-3) 14(16.7,-1) 15(18.7,-3) 16(18.7,-1) 17(20.7,-3) 18(20.7,-1) 19(22.7,-3) 20(22.7,-1)
  silkscreen extent 0,0 27.4,5.6
IDC2x17(2.0)B [mm]
  oval 0.9x1.2 hole 0.8: 1(4.7,-3) 2(4.7,-1) 3(6.7,-3) 4(6.7,-1) 5(8.7,-3) 6(8.7,-1) 7(10.7,-3) 8(10.7,-1) 9(12.7,-3) 10(12.7,-1) 11(14.7,-3) 12(14.7,-1) 13(16.7,-3) 14(16.7,-1) 15(18.7,-3) 16(18.7,-1) 17(20.7,-3) 18(20.7,-1) 19(22.7,-3) 20(22.7,-1) 21(24.7,-3) 22(24.7,-1) 23(26.7,-3) 24(26.7,-1) 25(28.7,-3) 26(28.7,-1) 27(30.7,-3) 28(30.7,-1) 29(32.7,-3) 30(32.7,-1) 31(34.7,-3) 32(34.7,-1) 33(36.7,-3) 34(36.7,-1)
  silkscreen extent 0,0 41.4,5.6
IDC2X30(2.0)B [mm]
  oval 0.9x1.2 hole 0.8: 1(4.7,-3) 2(4.7,-1) 3(6.7,-3) 4(6.7,-1) 5(8.7,-3) 6(8.7,-1) 7(10.7,-3) 8(10.7,-1) 9(12.7,-3) 10(12.7,-1) 11(14.7,-3) 12(14.7,-1) 13(16.7,-3) 14(16.7,-1) 15(18.7,-3) 16(18.7,-1) 17(20.7,-3) 18(20.7,-1) 19(22.7,-3) 20(22.7,-1) 21(24.7,-3) 22(24.7,-1) 23(26.7,-3) 24(26.7,-1) 25(28.7,-3) 26(28.7,-1) 27(30.7,-3) 28(30.7,-1) 29(32.7,-3) 30(32.7,-1) 31(34.7,-3) 32(34.7,-1) 33(36.7,-3) 34(36.7,-1) 35(38.7,-3) 36(38.7,-1) 37(40.7,-3) 38(40.7,-1) 39(42.7,-3) 40(42.7,-1) 41(44.7,-3) 42(44.7,-1) 43(46.7,-3) 44(46.7,-1) 45(48.7,-3) 46(48.7,-1) 47(50.7,-3) 48(50.7,-1) 49(52.7,-3) 50(52.7,-1) 51(54.7,-3) 52(54.7,-1) 53(56.7,-3) 54(56.7,-1) 55(58.7,-3) 56(58.7,-1) 57(60.7,-3) 58(60.7,-1) 59(62.7,-3) 60(62.7,-1)
  silkscreen extent 0,0 67.4,5.6
L7x7 [mm] "33uH"
  rect 2.2x3.2 smd: 1(-0.1,0) 2(5.7,0)
  silkscreen extent -0.2,-3.3 5.8,3.3
L1010 [mm] "33uH"
  rect 2.5x3.5 smd: 1(0,0) 2(9.4,0)
  silkscreen extent -0.3,-5 9.7,5
LED0603 [mm]
  rect 0.8x0.9 smd: 1(0,0) 2(1.7,0)
  silkscreen extent -0.68,-0.64 2.32,0.64
LQFP48 [mm] "LQFP, 48-Leads, Body 9.0x9.0mm (max), Pitch 0.50mm, IPC Medium Density"
  oval 1.65x0.3 smd: 1(-4.075,2.75) 2(-4.075,2.25) 3(-4.075,1.75) 4(-4.075,1.25) 5(-4.075,0.75) 6(-4.075,0.25) 7(-4.075,-0.25) 8(-4.075,-0.75) 9(-4.075,-1.25) 10(-4.075,-1.75) 11(-4.075,-2.25) 12(-4.075,-2.75) 25(4.075,-2.75) 26(4.075,-2.25) 27(4.075,-1.75) 28(4.075,-1.25) 29(4.075,-0.75) 30(4.075,-0.25) 31(4.075,0.25) 32(4.075,0.75) 33(4.075,1.25) 34(4.075,1.75) 35(4.075,2.25) 36(4.075,2.75)
  oval 0.3x1.65 smd: 13(-2.75,-4.075) 14(-2.25,-4.075) 15(-1.75,-4.075) 16(-1.25,-4.075) 17(-0.75,-4.075) 18(-0.25,-4.075) 19(0.25,-4.075) 20(0.75,-4.075) 21(1.25,-4.075) 22(1.75,-4.075) 23(2.25,-4.075) 24(2.75,-4.075) 37(2.75,4.075) 38(2.25,4.075) 39(1.75,4.075) 40(1.25,4.075) 41(0.75,4.075) 42(0.25,4.075) 43(-0.25,4.075) 44(-0.75,4.075) 45(-1.25,4.075) 46(-1.75,4.075) 47(-2.25,4.075) 48(-2.75,4.075)
  silkscreen extent -4.2,-2.85 2.85,3.58
M2.5-D5xH4 [mm]
  round 5.6 smd: 1(0,0)
  round 1.6 hole 1: 1(0,0)
M-4 [mm]
  round 4.6 hole 4: 1(0,0)
PH-2B [mm]
  rect 2.8x1.4 smd: 0(4.7,7.5) 0(4.7,0.5)
  rect 2.2x1 smd: 1(-2,5) 2(-2,3)
  silkscreen extent -1.6,0 6,8
PLCC32S1 [mil]
  rect 25x86.61 smd: 1(0,0)
  oval 25x86.61 smd: 2(-50,0) 3(-100,0) 4(-150,0) 14(-150,-530) 15(-100,-530) 16(-50,-530) 17(0,-530) 18(50,-530) 19(100,-530) 20(150,-530) 30(150,0) 31(100,0) 32(50,0)
  oval 86.61x25 smd: 5(-215,-65) 6(-215,-115) 7(-215,-165) 8(-215,-215) 9(-215,-265) 10(-215,-315) 11(-215,-365) 12(-215,-415) 13(-215,-465) 21(215,-465) 22(215,-415) 23(215,-365) 24(215,-315) 25(215,-265) 26(215,-215) 27(215,-165) 28(215,-115) 29(215,-65)
  silkscreen extent -345,-660 345,130
QFP208 [mm]
  oval 0.3x1.8 smd: 1(0,0) 2(0.5,0) 3(1,0) 4(1.5,0) 5(2,0) 6(2.5,0) 7(3,0) 8(3.5,0) 9(4,0) 10(4.5,0) 11(5,0) 12(5.5,0) 13(6,0) 14(6.5,0) 15(7,0) 16(7.5,0) 17(8,0) 18(8.5,0) 19(9,0) 20(9.5,0) 21(10,0) 22(10.5,0) 23(11,0) 24(11.5,0) 25(12,0) 26(12.5,0) 27(13,0) 28(13.5,0) 29(14,0) 30(14.5,0) 31(15,0) 32(15.5,0) 33(16,0) 34(16.5,0) 35(17,0) 36(17.5,0) 37(18,0) 38(18.5,0) 39(19,0) 40(19.5,0) 41(20,0) 42(20.5,0) 43(21,0) 44(21.5,0) 45(22,0) 46(22.5,0) 47(23,0) 48(23.5,0) 49(24,0) 50(24.5,0) 51(25,0) 52(25.5,0) 105(25.5,30.788) 106(25,30.788) 107(24.5,30.788) 108(24,30.788) 109(23.5,30.788) 110(23,30.788) 111(22.5,30.788) 112(22,30.788) 113(21.5,30.788) 114(21,30.788) 115(20.5,30.788) 116(20,30.788) 117(19.5,30.788) 118(19,30.788) 119(18.5,30.788) 120(18,30.788) 121(17.5,30.788) 122(17,30.788) 123(16.5,30.788) 124(16,30.788) 125(15.5,30.788) 126(15,30.788) 127(14.5,30.788) 128(14,30.788) 129(13.5,30.788) 130(13,30.788) 131(12.5,30.788) 132(12,30.788) 133(11.5,30.788) 134(11,30.788) 135(10.5,30.788) 136(10,30.788) 137(9.5,30.788) 138(9,30.788) 139(8.5,30.788) 140(8,30.788) 141(7.5,30.788) 142(7,30.788) 143(6.5,30.788) 144(6,30.788) 145(5.5,30.788) 146(5,30.788) 147(4.5,30.788) 148(4,30.788) 149(3.5,30.788) 150(3,30.788) 151(2.5,30.788) 152(2,30.788) 153(1.5,30.788) 154(1,30.788) 155(0.5,30.788) 156(0,30.788)
  oval 1.8x0.3 smd: 53(28.158,2.658) 54(28.158,3.158) 55(28.158,3.658) 56(28.158,4.158) 57(28.158,4.658) 58(28.158,5.158) 59(28.158,5.658) 60(28.158,6.158) 61(28.158,6.658) 62(28.158,7.158) 63(28.158,7.658) 64(28.158,8.158) 65(28.158,8.658) 66(28.158,9.158) 67(28.158,9.658) 68(28.158,10.158) 69(28.158,10.658) 70(28.158,11.158) 71(28.158,11.658) 72(28.158,12.158) 73(28.158,12.658) 74(28.158,13.158) 75(28.158,13.658) 76(28.158,14.158) 77(28.158,14.658) 78(28.158,15.158) 79(28.158,15.658) 80(28.158,16.158) 81(28.158,16.658) 82(28.158,17.158) 83(28.158,17.658) 84(28.158,18.158) 85(28.158,18.658) 86(28.158,19.158) 87(28.158,19.658) 88(28.158,20.158) 89(28.158,20.658) 90(28.158,21.158) 91(28.158,21.658) 92(28.158,22.158) 93(28.158,22.658) 94(28.158,23.158) 95(28.158,23.658) 96(28.158,24.158) 97(28.158,24.658) 98(28.158,25.158) 99(28.158,25.658) 100(28.158,26.158) 101(28.158,26.658) 102(28.158,27.158) 103(28.158,27.658) 104(28.158,28.158) 157(-2.658,28.158) 158(-2.658,27.658) 159(-2.658,27.158) 160(-2.658,26.658) 161(-2.658,26.158) 162(-2.658,25.658) 163(-2.658,25.158) 164(-2.658,24.658) 165(-2.658,24.158) 166(-2.658,23.658) 167(-2.658,23.158) 168(-2.658,22.658) 169(-2.658,22.158) 170(-2.658,21.658) 171(-2.658,21.158) 172(-2.658,20.658) 173(-2.658,20.158) 174(-2.658,19.658) 175(-2.658,19.158) 176(-2.658,18.658) 177(-2.658,18.158) 178(-2.658,17.658) 179(-2.658,17.158) 180(-2.658,16.658) 181(-2.658,16.158) 182(-2.658,15.658) 183(-2.658,15.158) 184(-2.658,14.658) 185(-2.658,14.158) 186(-2.658,13.658) 187(-2.658,13.158) 188(-2.658,12.658) 189(-2.658,12.158) 190(-2.658,11.658) 191(-2.658,11.158) 192(-2.658,10.658) 193(-2.658,10.158) 194(-2.658,9.658) 195(-2.658,9.158) 196(-2.658,8.658) 197(-2.658,8.158) 198(-2.658,7.658) 199(-2.658,7.158) 200(-2.658,6.658) 201(-2.658,6.158) 202(-2.658,5.658) 203(-2.658,5.158) 204(-2.658,4.658) 205(-2.658,4.158) 206(-2.658,3.658) 207(-2.658,3.158) 208(-2.658,2.658)
  silkscreen extent -3.3,-1.84 28.7,31.4
R0603 [mil]
  rect 38x35 smd: 1(0,0) 2(65,0)
  silkscreen extent -25,-25 90,25
SO-8 [mil]
  rect 80x24 smd: 1(0,0)
  oval 80x24 smd: 2(0,-50) 3(0,-100) 4(0,-150) 5(220,-150) 6(220,-100) 7(220,-50) 8(220,0)
  silkscreen extent 60,-175 160,25
"SO-8 A" [mil]
  rect 78.74x157.48 smd: 0(110,-75)
  rect 80x24 smd: 1(0,0)
  oval 80x24 smd: 2(0,-50) 3(0,-100) 4(0,-150) 5(220,-150) 6(220,-100) 7(220,-50) 8(220,0)
  silkscreen extent 60,-175 160,25
SO-14 [mil]
  oval 80x22 smd: 1(0,0) 2(0,-50) 3(0,-100) 4(0,-150) 5(0,-200) 6(0,-250) 7(0,-300) 8(220,-300) 9(220,-250) 10(220,-200) 11(220,-150) 12(220,-100) 13(220,-50) 14(220,0)
  silkscreen extent 60,-325 160,25
SO-16 [mil]
  oval 80x22 smd: 1(0,0) 2(0,-50) 3(0,-100) 4(0,-150) 5(0,-200) 6(0,-250) 7(0,-300) 8(0,-350) 9(220,-350) 10(220,-300) 11(220,-250) 12(220,-200) 13(220,-150) 14(220,-100) 15(220,-50) 16(220,0)
  silkscreen extent 60,-375 160,25
SOD123 [mm]
  rect 1x1 smd: A(0,0) K(3.6,0)
  silkscreen extent 0.69,-0.9 2.93,0.9
SOJ-42 [mil] "薄贴片"
  oval 80x24 smd: 1(0,0) 2(0,-50) 3(0,-100) 4(0,-150) 5(0,-200) 6(0,-250) 7(0,-300) 8(0,-350) 9(0,-400) 10(0,-450) 11(0,-500) 12(0,-550) 13(0,-600) 14(0,-650) 15(0,-700) 16(0,-750) 17(0,-800) 18(0,-850) 19(0,-900) 20(0,-950) 21(0,-1000) 22(409.45,-1000) 23(409.45,-950) 24(409.45,-900) 25(409.45,-850) 26(409.45,-800) 27(409.45,-750) 28(409.45,-700) 29(409.45,-650) 30(409.45,-600) 31(409.45,-550) 32(409.45,-500) 33(409.45,-450) 34(409.45,-400) 35(409.45,-350) 36(409.45,-300) 37(409.45,-250) 38(409.45,-200) 39(409.45,-150) 40(409.45,-100) 41(409.45,-50) 42(409.45,0)
  silkscreen extent -8,-1031 417,31
SOP16 [mil]
  oval 66.93x22 smd: 1(0,0) 2(0,-50) 3(0,-100) 4(0,-150) 5(0,-200) 6(0,-250) 7(0,-300) 8(0,-350) 9(281.34,-350) 10(281.34,-300) 11(281.34,-250) 12(281.34,-200) 13(281.34,-150) 14(281.34,-100) 15(281.34,-50) 16(281.34,0)
  silkscreen extent 51,-378 228,28
SOP20B [mil]
  oval 66.93x22 smd: 1(0,0) 2(0,-50) 3(0,-100) 4(0,-150) 5(0,-200) 6(0,-250) 7(0,-300) 8(0,-350) 9(0,-400) 10(0,-450) 11(400,-450) 12(400,-400) 13(400,-350) 14(400,-300) 15(400,-250) 16(400,-200) 17(400,-150) 18(400,-100) 19(400,-50) 20(400,0)
  silkscreen extent 46,-481 354,31
SOP24-B [mm]
  rect 0.508x2.1 smd: 1(0,0.2) 2(1.27,0.2) 3(2.54,0.2) 4(3.81,0.2) 5(5.08,0.2) 6(6.35,0.2) 7(7.62,0.2) 8(8.89,0.2) 9(10.16,0.2) 10(11.43,0.2) 11(12.7,0.2) 12(13.97,0.2) 13(13.97,11.6) 14(12.7,11.6) 15(11.43,11.6) 16(10.16,11.6) 17(8.89,11.6) 18(7.62,11.6) 19(6.35,11.6) 20(5.08,11.6) 21(3.81,11.6) 22(2.54,11.6) 23(1.27,11.6) 24(0,11.6)
  silkscreen extent -1.14,0.51 14.73,10.3
SOP-28 [mm]
  oval 0.635x1.9 smd: 1(0,0) 2(1.27,0) 3(2.54,0) 4(3.81,0) 5(5.08,0) 6(6.35,0) 7(7.62,0) 8(8.89,0) 9(10.16,0) 10(11.43,0) 11(12.7,0) 12(13.97,0) 13(15.24,0) 14(16.51,0) 15(16.51,10) 16(15.24,10) 17(13.97,10) 18(12.7,10) 19(11.43,10) 20(10.16,10) 21(8.89,10) 22(7.62,10) 23(6.35,10) 24(5.08,10) 25(3.81,10) 26(2.54,10) 27(1.27,10) 28(0,10)
  silkscreen extent -1.14,0.41 17.27,8.8
SOT23 [mil]
  rect 36x36 smd: B(-37.5,-40) E(37.5,-40)
  rect 36x50 smd: C(0.5,40)
  silkscreen extent -58,-45 58,45
SW3 [mm]
  oval 1.4x2 hole 0.6 slot 1.1 at 90 deg: 0(0.3,1.3)
  oval 2x1.4 hole 0.6 slot 1 at 0 deg: 0(12.2,4.8)
  oval 1.016x1.4 hole 0.8: 1(8.5,2.6) 2(6,2.6) 3(3.5,2.6)
  silkscreen extent 0,-0.5 25.4,5.7
TO-252-MOS [mm] "D2-PAK/TO-263-AB; 3 Leads (1 Cropped); Body 15.5 (inc. leads) x 10.5 mm (LxW max)"
  rect 1.6x3.2 smd: 1(0,0) 2(4.6,0)
  rect 7x6 smd: 3(2.3,6.8)
  silkscreen extent -1.4,3 6,10
TO-263(T) [mil]
  rect 420x350 smd: 0(133,375)
  rect 42x140 smd: 1(0,0) 2(68,0) 3(134,0) 4(199,0) 5(266,0)
  silkscreen extent -77,177 343,555
USBA-S [mm]
  rect 1.8x2 smd: 0(1.6,14.2) 0(1.6,-1) 0(7.6,-1) 0(7.6,14.2)
  oval 3x1.2 smd: D+(-0.9,7.6) D-(-0.9,5.6) GND(-0.9,10.1) VCC(-0.9,3.1)
  silkscreen extent 0,0 10,13.2
VR3362 [mm]
  round 1.2 hole 0.7: 1(0.95,3.6) 2(5.95,3.6) W(3.45,6.1)
  silkscreen extent 0,0 6.9,7.1

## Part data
BAT1 J2 J3: library part CON2
C1 C2 C3 C4 C5 C6 C7 C8 C9 C10 C11 C12 C13 C14 C15 C16 C17 C30 C31 C43 C44 C45 C46 C47 C48 C49 C50 C53 C58 C59 C60 C61 C68 C72 C73 C74 C75 C76 C77 C78 C80 C83 C84 C85 C86 C87 C88 C89 C90 C91 C92 C93 C94 C95 C96 C97 C98 C99 C100 C101 C102 C103 C104 C106: library part 0CAP
C18 C21 C23 C24: library part 0CAP1
C19 C20 C22 C25 C26 C27 C28 C29 C52 C54 C55 C56 C57 C62 C63 C64 C65 C66 C105 C108 C109 C110 C111 C112 C113 C114 C115 C116 C121: library part CAP
D3 D4 D5 D7 D20: library part 0DIODE
D8 D9 D10 D11 D12: library part DIODE1
FU1 R1 R3 R8 R9 R10 R11 R12 R15 R16 R24 R28 R29 R31 R32 R44 R45 R46 R47 R48 R49 R50 R51 R52 R53 R54 R55 R56 R57 R58 R59 R60 R61 R62 R63 R64 R65 R66 R67 R68 R69 R70 R81 R82: library part 0RES
J4: "Connector"
L3 L4 L5: library part L
LED1 LED2 LED3 LED4 LED5 LED6: library part 0LED
Q1: library part 0NPN
Q2: library part MOSFET-P, "P-Channel MOSFET", PackageDocument=1995/1996
Q3: library part MOS-SO-8
R2 R22 R23 R25 R26 R27 R34 R35 R38 R100 R101 R102 R103 R104 R105 R106 R107 R108 R109 R124 R130 R131 R132 R133 R134 R135 R136 R137 R138 R139: library part RES2
SP1: library part BELL
SW1: library part SW1_1
T1 T2 T3 T4 T5 T6 T7 T8: library part CON1
U12: library part CH375
U15 U16: library part OPA-2
U17 U18 U19 U20: library part 74LS139
U40: library part STC8G2K64S2-48_B
VR1 VR2: library part VR
X1 X2: library part CRYSTAL-4P
X3 X4: library part CRYSTAL

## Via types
v1: diameter 20, hole 12, Top Layer to Bottom Layer, tented both sides, 1165 vias
v2: diameter 19.68, hole 11.81, Top Layer to Bottom Layer, tented both sides, 10 vias
v3: diameter 27.56, hole 27.56, Top Layer to Bottom Layer, 4 vias
v4: diameter 35.43, hole 35.43, Top Layer to Bottom Layer, 2 vias
v5: diameter 55.12, hole 55.12, Top Layer to Bottom Layer, 2 vias
v6: diameter 66.93, hole 66.93, Top Layer to Bottom Layer, 2 vias
v7: diameter 78.74, hole 78.74, Top Layer to Bottom Layer, 1 vias

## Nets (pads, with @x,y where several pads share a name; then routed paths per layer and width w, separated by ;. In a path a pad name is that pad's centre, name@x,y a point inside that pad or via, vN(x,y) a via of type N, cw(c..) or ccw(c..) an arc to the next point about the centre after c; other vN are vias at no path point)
0WS#: R53.1 U1.165 | length 278.4
  Top Layer w8: v1(10450,1660) 10452.3,1657.7 10460.77,1657.7 10515.02,1603.45 10515.02,1568.29 U1.165@10515.75,1567.56
  Bottom Layer w8: v1(10450,1660) 10450,1734.5 10505,1789.5 R53.1@10505,1791
1A: R28.1 U14.10 | length 122
  Top Layer w12: R28.1@7387,2703 7398.5,2691.5 7400.5,2691.5 7459,2633 U14.10@7480,2633
2A: R31.1 U14.11 | length 91.7
  Top Layer w12: R31.1@7393,2571.67 7402.42,2581.09 7478.09,2581.09 U14.11@7480,2583
+12V: FU1.2 J1.46 | length 6611.3
  Top Layer w40: FU1.2@6659.11,4263 6659.11,4376.11 6711,4428 8334,4428 8495,4267 8759,4267 8928,4436 10410,4436 10593,4253 10757,4253 10938,4434 12729,4434 12767.72,4395.28 J1.46@12767.72,4330.71
A0: CF1.20 J1.1 J6.57 J7.57 U1.195 U8.12 U10.4 U12.8 U20.2 U20.14 | length 13950.9
  Top Layer w8: v1(7787,3571) 7789.3,3573.3 7796.87,3573.3 7797.69,3574.12 8335.33,3574.12 8366.14,3543.31 8830.71,3543.31 8967,3407.02 8967,3067.75 8966.7,3067.44 8966.7,3065.07 8954,3052.37 8954,3012.77 8917.6,2976.38 J6.57@8838.58,2976.38 ; v1(7788,3316) U10.4@7788,3375.82 ; J7.57@9692.91,2976.38 9693.64,2977.1 9743.73,2977.1 9881.63,3115 9923.5,3115 9924.5,3116 10055.6,3116 10056.6,3115 v1(10189,3115) 10189.7,3115.7 10886.67,3115.7 10964.37,3038 11546.25,3038 12042.9,3534.65 CF1.20@12147.64,3534.65 ; U1.195@9925.2,1567.56 9925.2,1667.2 10023.17,1765.17 10069.17,1765.17 10189,1885 10189,1980.15 10198.39,1989.55 v1(10198.39,1990.84) 10198.73,1991.17 10213.17,1991.17 10461,2239 11176.97,2239 11228.97,2291 11310,2291 v1(11310.7,2291.7) ; U8.12@11346.46,1953.62 11346.46,1853.54 11365.39,1834.61 v1(11366.61,1834.61) 11397.23,1804 11646.03,1804 11706.15,1864.12 12137.88,1864.12 12157.6,1844.4 12387.6,1844.4 12463.1,1768.9 U12.8@12629.92,1768.9 12629.97,1768.95 12679.84,1768.95 12679.89,1769 12755.65,1769 12755.7,1768.95 12836.95,1768.95 v1(12837,1769) 12881,1725 13127,1725 13149,1703 v1(13302,1703)
  Layer 2 w8: v1(8954,3013) 8954,3014.83 9097.17,3158 9343.51,3158 9461.07,3040.44 9762.44,3040.44 9838,3116 v1(9923.5,3116)
  Bottom Layer w8: v1(7787,3571) 7787.5,3570.5 7787.5,3316.5 v1(7788,3316) ; v1(10198.39,1990.84) 10199,1991.45 10199,3046.06 10189,3056.06 v1(10189,3115) 10189,4031.39 10409.58,4251.97 J1.1@11035.43,4251.97 ; v1(11310.7,2291.7) 11312.98,2289.42 11312.98,2198.02 11336,2175 11336,2090 11360.32,2065.68 11360.32,1879.42 11366.61,1873.13 v1(11366.61,1834.61) ; v1(12837,1769) 12837,1841.74 12900.76,1905.5 12950.45,1905.5 U20.14@12952.76,1907.8 ; U20.2@13172.76,1957.8 13235.94,1957.8 13279,1914.75 13279,1848 13303,1824 13303,1704 v1(13302,1703)
A1: CF1.19 J1.3 J6.55 J7.55 U1.194 U8.11 U10.5 U20.3 U20.13 | length 13988.9
  Top Layer w8: v1(7737,3315) 7737.5,3315.5 7737.5,3375.32 U10.5@7738,3375.82 ; v1(7738,3562) 7769,3593 8340.41,3593 8374.1,3559.31 8837.34,3559.31 8983,3413.64 8983,3061.12 8982.7,3060.82 8982.7,3017.84 8980.63,3015.77 v1@8980.63,3014.37 ; J6.55@8838.58,2956.69 8928.81,2956.69 8982.7,3010.59 v1(8982.7,3012.3) ; J7.55@9685.04,2956.69 9685.76,2957.42 9746.67,2957.42 9882.96,3093.7 v1(9947,3093.7) 9947.7,3093 10210.42,3093 v1(10211.12,3093.7) ; U1.194@9944.88,1567.56 9944.88,1664.25 10029.79,1749.17 10075.79,1749.17 10211,1884.37 v1(10211,1915.11) 10211,1964 10470,2223 11183.6,2223 11229.91,2269.31 11319.43,2269.31 11339.89,2289.77 11390.09,2289.77 11410.03,2269.84 v1(11417.05,2269.84) ; v1@10211.28,3093 10886.75,3093 10957.75,3022 11552.88,3022 12015.53,3484.65 CF1.19@12147.64,3484.65 ; U8.11@11396.46,1953.62 11396.46,1921.18 11396.51,1921.18 11425,1892.69 v1(11425,1891.11) ; v1@11419.11,2271.89 11419.11,2271.03 11426.3,2263.84 11427.16,2263.84 11443,2248 11498,2248 11569,2177 11803,2177 11831,2149 11936,2149 11965,2178 12307.37,2178 12338.37,2147 12721.37,2147 12745.37,2171 13088.11,2171 v1(13104,2186.89) ; v1(12895,1857) 13067,1857 13088,1878 v1(13111,1878)
  Layer 2 w8: v1(8982.7,3012.3) 8982.7,3015.55 9109.15,3142 9336.88,3142 9454.44,3024.44 9769.07,3024.44 9838.33,3093.7 v1(9947,3093.7)
  Bottom Layer w8: v1(7737,3315) 7737.5,3315.5 v1@7737.5,3562 ; v1(10211,1915.11) 10212,1916.11 10212,1964.98 10224,1976.98 10224,1995.2 10217.56,2001.64 10217.56,3050.13 10211.12,3056.57 10211.12,3092.72 v1@10211,3092.85 ; v1(10211.12,3093.7) 10211,3093.82 10211,4030.76 10416.2,4235.97 10971.03,4235.97 10993,4214 11082.11,4214 11114.17,4246.06 J1.3@11114.17,4251.97 ; v1(11417.05,2269.84) 11419,2267.89 11419,2161.44 11412,2154.44 11412,1907.25 11425,1894.25 v1(11425,1891.11) ; v1(12895,1857) 12895.4,1857.4 12919.57,1857.4 12919.97,1857.8 U20.13@12952.76,1857.8 ; v1(13104,2186.89) 13104,2186.2 13094,2176.2 13094,1897.77 13111,1880.77 v1(13111,1878) 13112.48,1878 13142.28,1907.8 U20.3@13172.76,1907.8
A2: CF1.18 J1.5 J6.53 J7.53 U1.193 U8.10 | length 9252.9
  Top Layer w8: J6.53@8838.58,2937.01 8938.52,2937.01 v1(9011.51,3010) ; J7.53@9685.76,2937.73 9749.61,2937.73 9882.88,3071 9922.8,3071 v1(9923.5,3071.7) 10233.3,3071.7 v1(10234,3071) 10880.43,3071 10945.43,3006 11563,3006 11991.65,3434.65 CF1.18@12147.64,3434.65 ; U1.193@9964.57,1567.56 9964.57,1661.31 10036.42,1733.17 10082.42,1733.17 10234,1884.75 v1(10234,1947.2) ; v1@10234,1948 10236.3,1950.3 10236.3,1962.8 10480.5,2207 11190.22,2207 11236.54,2253.31 11331.29,2253.31 11345.75,2267.77 v1(11349,2267.77) ; v1(11358,2109) 11361,2109 11446.46,2023.54 U8.10@11446.46,1953.62
  Layer 2 w8: v1(9011.51,3010) 9127.51,3126 9330.26,3126 9447.81,3008.44 9775.7,3008.44 9838.66,3071.4 9923.2,3071.4 v1(9923.5,3071.7)
  Bottom Layer w8: v1(10234,1947.2) 10234,1950.45 10240,1956.45 10240,2001.83 10234,2007.83 v1(10234,3071) 10234,4031.14 10422.83,4219.97 10961.58,4219.97 10985.54,4196 11142.85,4196 11192.91,4246.06 J1.5@11192.91,4251.97 ; v1(11349,2267.77) 11348,2266.77 11348,2195.85 11358,2185.85 v1(11358,2109)
A3: J1.7 J6.51 J7.51 U1.192 U8.9 U19.2 U25.1 | length 8708
  Top Layer w8: J6.51@8838.58,2917.32 8950.21,2917.32 v1(9039.28,3006.39) ; J7.51@9685.04,2917.32 9751.83,2917.32 9883.51,3049 v1(9949,3049) ; v1@9952,3049 v1(10256,3049) ; U1.192@9984.25,1567.56 9984.25,1658.37 10043.05,1717.17 10089.05,1717.17 10256,1884.12 v1(10256,1914) 10256,1959.88 10487.12,2191 11196.85,2191 11243.16,2237.31 11349.65,2237.31 11361.34,2249 v1(11396,2249) 11397.16,2247.84 11420.54,2247.84 11436.37,2232 11491.37,2232 11570.37,2153 11791.89,2153 v1(11793.89,2155) ; v1(11443,1864) 11469,1864 11496.46,1891.46 U8.9@11496.46,1953.62
  Layer 2 w8: v1(9039.28,3006.39) 9039.28,3006.79 9060.29,3027.8 9060.69,3027.8 9142.89,3110 9323.63,3110 9441.18,2992.44 9787.44,2992.44 9844,3049 v1(9949,3049)
  Bottom Layer w8: v1(10256,1914) v1(10256,3049) 10256,4030.51 10429.46,4203.97 10954.95,4203.97 10978.92,4180 11205.59,4180 11271.65,4246.06 J1.7@11271.65,4251.97 ; v1(11443,1864) 11421,1864 11402.49,1882.51 11396,1889 v1(11396,2249) 11395,2250 11395,2415 11447,2467 11598,2467 11674.7,2543.7 U25.1@11740.16,2543.7 ; U19.2@11740.16,1957.8 11769.16,1957.8 11792.16,1980.8 11792.16,2153.27 v1(11793.89,2155)
A4: J1.9 J6.49 J7.49 U1.191 U8.8 U17.1 U25.2 | length 9457.4
  Top Layer w8: J6.49@8838.58,2897.64 8961.64,2897.64 9069.4,3005.4 v1(9069.4,3005.8) ; J7.49@9685.04,2897.64 9754.77,2897.64 9882.14,3025 9923.5,3025 9925.31,3026.81 10099.7,3026.81 10101.51,3025 v1(10278,3025) ; U1.191@10003.94,1567.56 10003.94,1655.43 10049.68,1701.17 10095.68,1701.17 10278,1883.49 v1(10278,1949) 10280.3,1951.3 10280.3,1961.55 10493.75,2175 11203.48,2175 11249.48,2221 v1(11371,2221) 11424.75,2221 11429.75,2216 11484.75,2216 11567.75,2133 11949.37,2133 11972.37,2156 v1(12298.26,2156) ; v1(11424.06,1842) 11425.06,1841 11502,1841 11546.46,1885.46 U8.8@11546.46,1953.62
  Layer 2 w8: v1(9069.4,3005.8) 9069.4,3006.2 9157.2,3094 9317,3094 9434.56,2976.44 9794.07,2976.44 9844.44,3026.81 v1(9923.5,3026.81)
  Bottom Layer w8: v1(10278,1949) v1(10278,3025) 10278,4029.88 10436.09,4187.97 10948.32,4187.97 10972.29,4164 11219.06,4164 11271.06,4216 11320.33,4216 11350.39,4246.06 J1.9@11350.39,4251.97 ; v1(11424.06,1842) 11420.81,1842 11414.81,1848 11414.37,1848 11380,1882.37 11380,2195 11373.3,2201.7 11373.3,2218.7 v1(11371,2221) 11371,2434 11456,2519 11618,2519 11673,2574 11783,2574 11798,2559 11798,2518.75 11772.95,2493.7 U25.2@11740.16,2493.7 ; U17.1@12263.78,2007.8 12282.31,2007.8 12288.78,2014.27 12288.78,2143.27 12298.26,2152.75 v1(12298.26,2156)
A5: J1.11 J6.47 J7.47 U1.190 U8.7 U17.2 U25.3 | length 8796.1
  Top Layer w8: J6.47@8838.58,2877.95 8975.99,2877.95 v1(9001.04,2903) ; J7.47@9685.04,2877.95 9757.72,2877.95 9884.28,3004.52 v1(9947,3004.52) 9948.52,3003 10298.48,3003 v1(10300,3004.52) ; U1.190@10023.62,1567.56 10023.62,1652.25 10056.54,1685.17 10102.3,1685.17 10300,1882.86 v1(10300,1914) 10300,1958.62 10500.38,2159 11210.11,2159 11250.11,2199 11479.12,2199 11567.12,2111 v1(11597,2111) ; v1(11596,2017) 11596.23,2016.77 11596.23,1953.85 U8.7@11596.46,1953.62 ; v1@11597,2113 11952,2113 11973,2134 12316,2134 v1(12333,2117)
  Layer 2 w8: v1(9001.04,2903) 9001.04,2905.13 9145.77,3049.86 9237.11,3049.86 9258.98,3028 9360.37,3028 9427.93,2960.44 9800.7,2960.44 9844.77,3004.52 v1(9947,3004.52)
  Bottom Layer w8: v1(10300,1914) v1(10300,3004.52) 10300,4029.25 10442.71,4171.97 10941.69,4171.97 10965.66,4148 11225.69,4148 11277.69,4200 11383.07,4200 11429.13,4246.06 J1.11@11429.13,4251.97 ; v1(11596,2017) 11596.5,2017.5 11596.5,2110.5 v1(11597,2111) 11613,2127 11613,2418 11638.7,2443.7 U25.3@11740.16,2443.7 ; U17.2@12263.78,1957.8 12292.78,1957.8 12333,1998.02 v1(12333,2117)
A6: J1.13 J6.45 J7.45 U1.189 U8.6 U17.3 U25.4 | length 8756.6
  Top Layer w8: J6.45@8838.58,2858.27 8988.38,2858.27 9029.02,2898.91 v1(9029.02,2902) ; J7.45@9685.04,2858.27 9760.66,2858.27 9884.91,2982.52 v1(9923.5,2982.52) ; v1@9923.5,2980 9926.53,2980 9929.04,2982.52 10312.31,2982.52 10312.53,2982.3 10322.78,2982.3 v1(10323,2982.52) ; U1.189@10043.31,1567.56 10043.31,1649.31 10063,1669 10108.76,1669 10323,1883.24 v1(10323,1949) 10325.3,1951.3 10325.3,1961.29 10507.01,2143 11216.73,2143 11256.73,2183 11472.49,2183 11566.49,2089 11639,2089 v1(11641,2091) 11957,2091 11981,2115 12303,2115 12328,2090 v1(12355,2090) ; v1(11644,2017) 11645.23,2015.77 11645.23,1954.85 U8.6@11646.46,1953.62
  Layer 2 w8: v1(9029.02,2902) 9029.02,2905.11 9129.77,3005.86 9235.11,3005.86 9257.11,2983.86 9381.88,2983.86 9421.3,2944.44 9807.33,2944.44 9845.1,2982.22 9923.2,2982.22 v1(9923.5,2982.52)
  Bottom Layer w8: v1(10323,1949) 10323,2980 10323,4029.63 10449.34,4155.97 10935.07,4155.97 10959.03,4132 11232.32,4132 11284.32,4184 11445.81,4184 11507.87,4246.06 J1.13@11507.87,4251.97 ; v1@11640,2092 11642.5,2089.5 11642.5,2018.5 v1(11644,2017) ; v1(11641,2091) 11641,2092.69 11632,2101.69 11632,2364 11661.7,2393.7 U25.4@11740.16,2393.7 ; U17.3@12263.78,1907.8 12292.78,1907.8 12355,1970.02 v1(12355,2090)
A7: J1.15 J6.43 J7.43 U1.187 U8.5 U9.5 U18.15 U19.3 | length 9532
  Top Layer w8: J6.43@8838.58,2838.58 8997.7,2838.58 9040.68,2881.57 9040.68,2882.55 9057.02,2898.89 v1(9057.02,2902) ; J7.43@9685.04,2838.58 9763.6,2838.58 9885.24,2960.22 9946.7,2960.22 v1(9947,2960.52) ; v1@9947.48,2960.52 10334.31,2960.52 10334.53,2960.3 10344.63,2960.3 v1(10345,2959.92) ; U1.187@10082.68,1567.56 10082.68,1620.19 10345,1882.51 v1(10345,1916) 10345,1958.37 10513.63,2127 11223.36,2127 11263.36,2167 11465.86,2167 11565.86,2067 v1(11674,2067) 12132,2067 12158.4,2093.4 12291.6,2093.4 12319,2066 12474,2066 12506,2066 12568,2128 12725,2128 12752,2155 13094.74,2155 13100.74,2161 v1(13131,2161) ; v1(11675,2017) 11675,2013.75 11693.2,1995.55 11693.2,1956.87 U8.5@11696.46,1953.62
  Layer 2 w8: v1(9057.02,2902) 9057.02,2905.15 9113.47,2961.6 9237.11,2961.6 9260.71,2938 9405.12,2938 9414.67,2928.44 9813.95,2928.44 9846.03,2960.52 v1(9947,2960.52)
  Bottom Layer w8: v1(10345,1916) 10345,2958 10345,4029 10455.97,4139.97 10928.44,4139.97 10952.41,4116 11238.94,4116 11290.94,4168 11460,4168 11505,4213 11549.84,4213 11586.61,4249.78 J1.15@11586.61,4251.97 ; v1(11674,2067) 11674.5,2066.5 11674.5,2017.5 v1(11675,2017) 11675,1943.96 11711.16,1907.8 U19.3@11740.16,1907.8 ; v1(12474,2068) 12474,1986.3 12502.5,1957.8 U18.15@12531.5,1957.8 ; v1(13131,2161) 13131,2195 13101,2225 13101,2334 13110.7,2343.7 U9.5@13172.76,2343.7
A8: J1.17 J6.41 J7.41 U1.186 U8.27 U19.14 U25.6 | length 8413.2
  Top Layer w8: J6.41@8838.58,2818.9 9007.9,2818.9 9079.97,2890.97 9079.97,2893.74 9085.02,2898.79 v1(9085.02,2902.04) ; J7.41@9685.04,2818.9 9766.54,2818.9 9883.65,2936 9921.28,2936 v1(9923.5,2938.22) ; v1@9925.42,2937.92 10365.08,2937.92 v1(10367,2936) ; U1.186@10102.36,1567.56 10102.36,1617.24 10367,1881.88 v1(10367,1949) 10369.3,1951.3 10369.3,1960.04 10520.26,2111 11229.99,2111 11269.99,2151 11446,2151 11475.5,2121.5 11488.73,2121.5 11566.24,2044 v1(11698,2044) ; U8.27@11596.46,1523.62 11596.46,1703.46 v1(11624,1731)
  Layer 2 w8: v1(9085.02,2902.04) 9085.02,2904.13 9103.89,2923 9213.49,2923 9219.02,2917.47 9239.09,2917.47 9244.11,2912.44 9245.31,2912.44 9250,2907.76 9250,2906.55 9262.89,2893.66 9281.11,2893.66 9299.89,2912.44 9820.58,2912.44 9845.76,2937.63 9922.91,2937.63 v1(9923.5,2938.22)
  Bottom Layer w8: v1(10367,1949) v1(10367,2936) 10367,4028.37 10462.6,4123.97 10921.81,4123.97 10945.78,4100 11245.57,4100 11297.57,4152 11466.63,4152 11511.63,4197 11616.29,4197 11665.35,4246.06 J1.17@11665.35,4251.97 ; v1(11458,2139) 11456,2137 11456,1942.96 11491.16,1907.8 11549.16,1907.8 11624,1832.96 v1(11624,1731) ; v1(11698,2044) 11698,2118 11658,2158 11658,2277.4 11674.3,2293.7 U25.6@11740.16,2293.7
